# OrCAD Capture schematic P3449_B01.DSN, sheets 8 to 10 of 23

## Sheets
8 0015_Gigabit Ethernet POE: size Custom
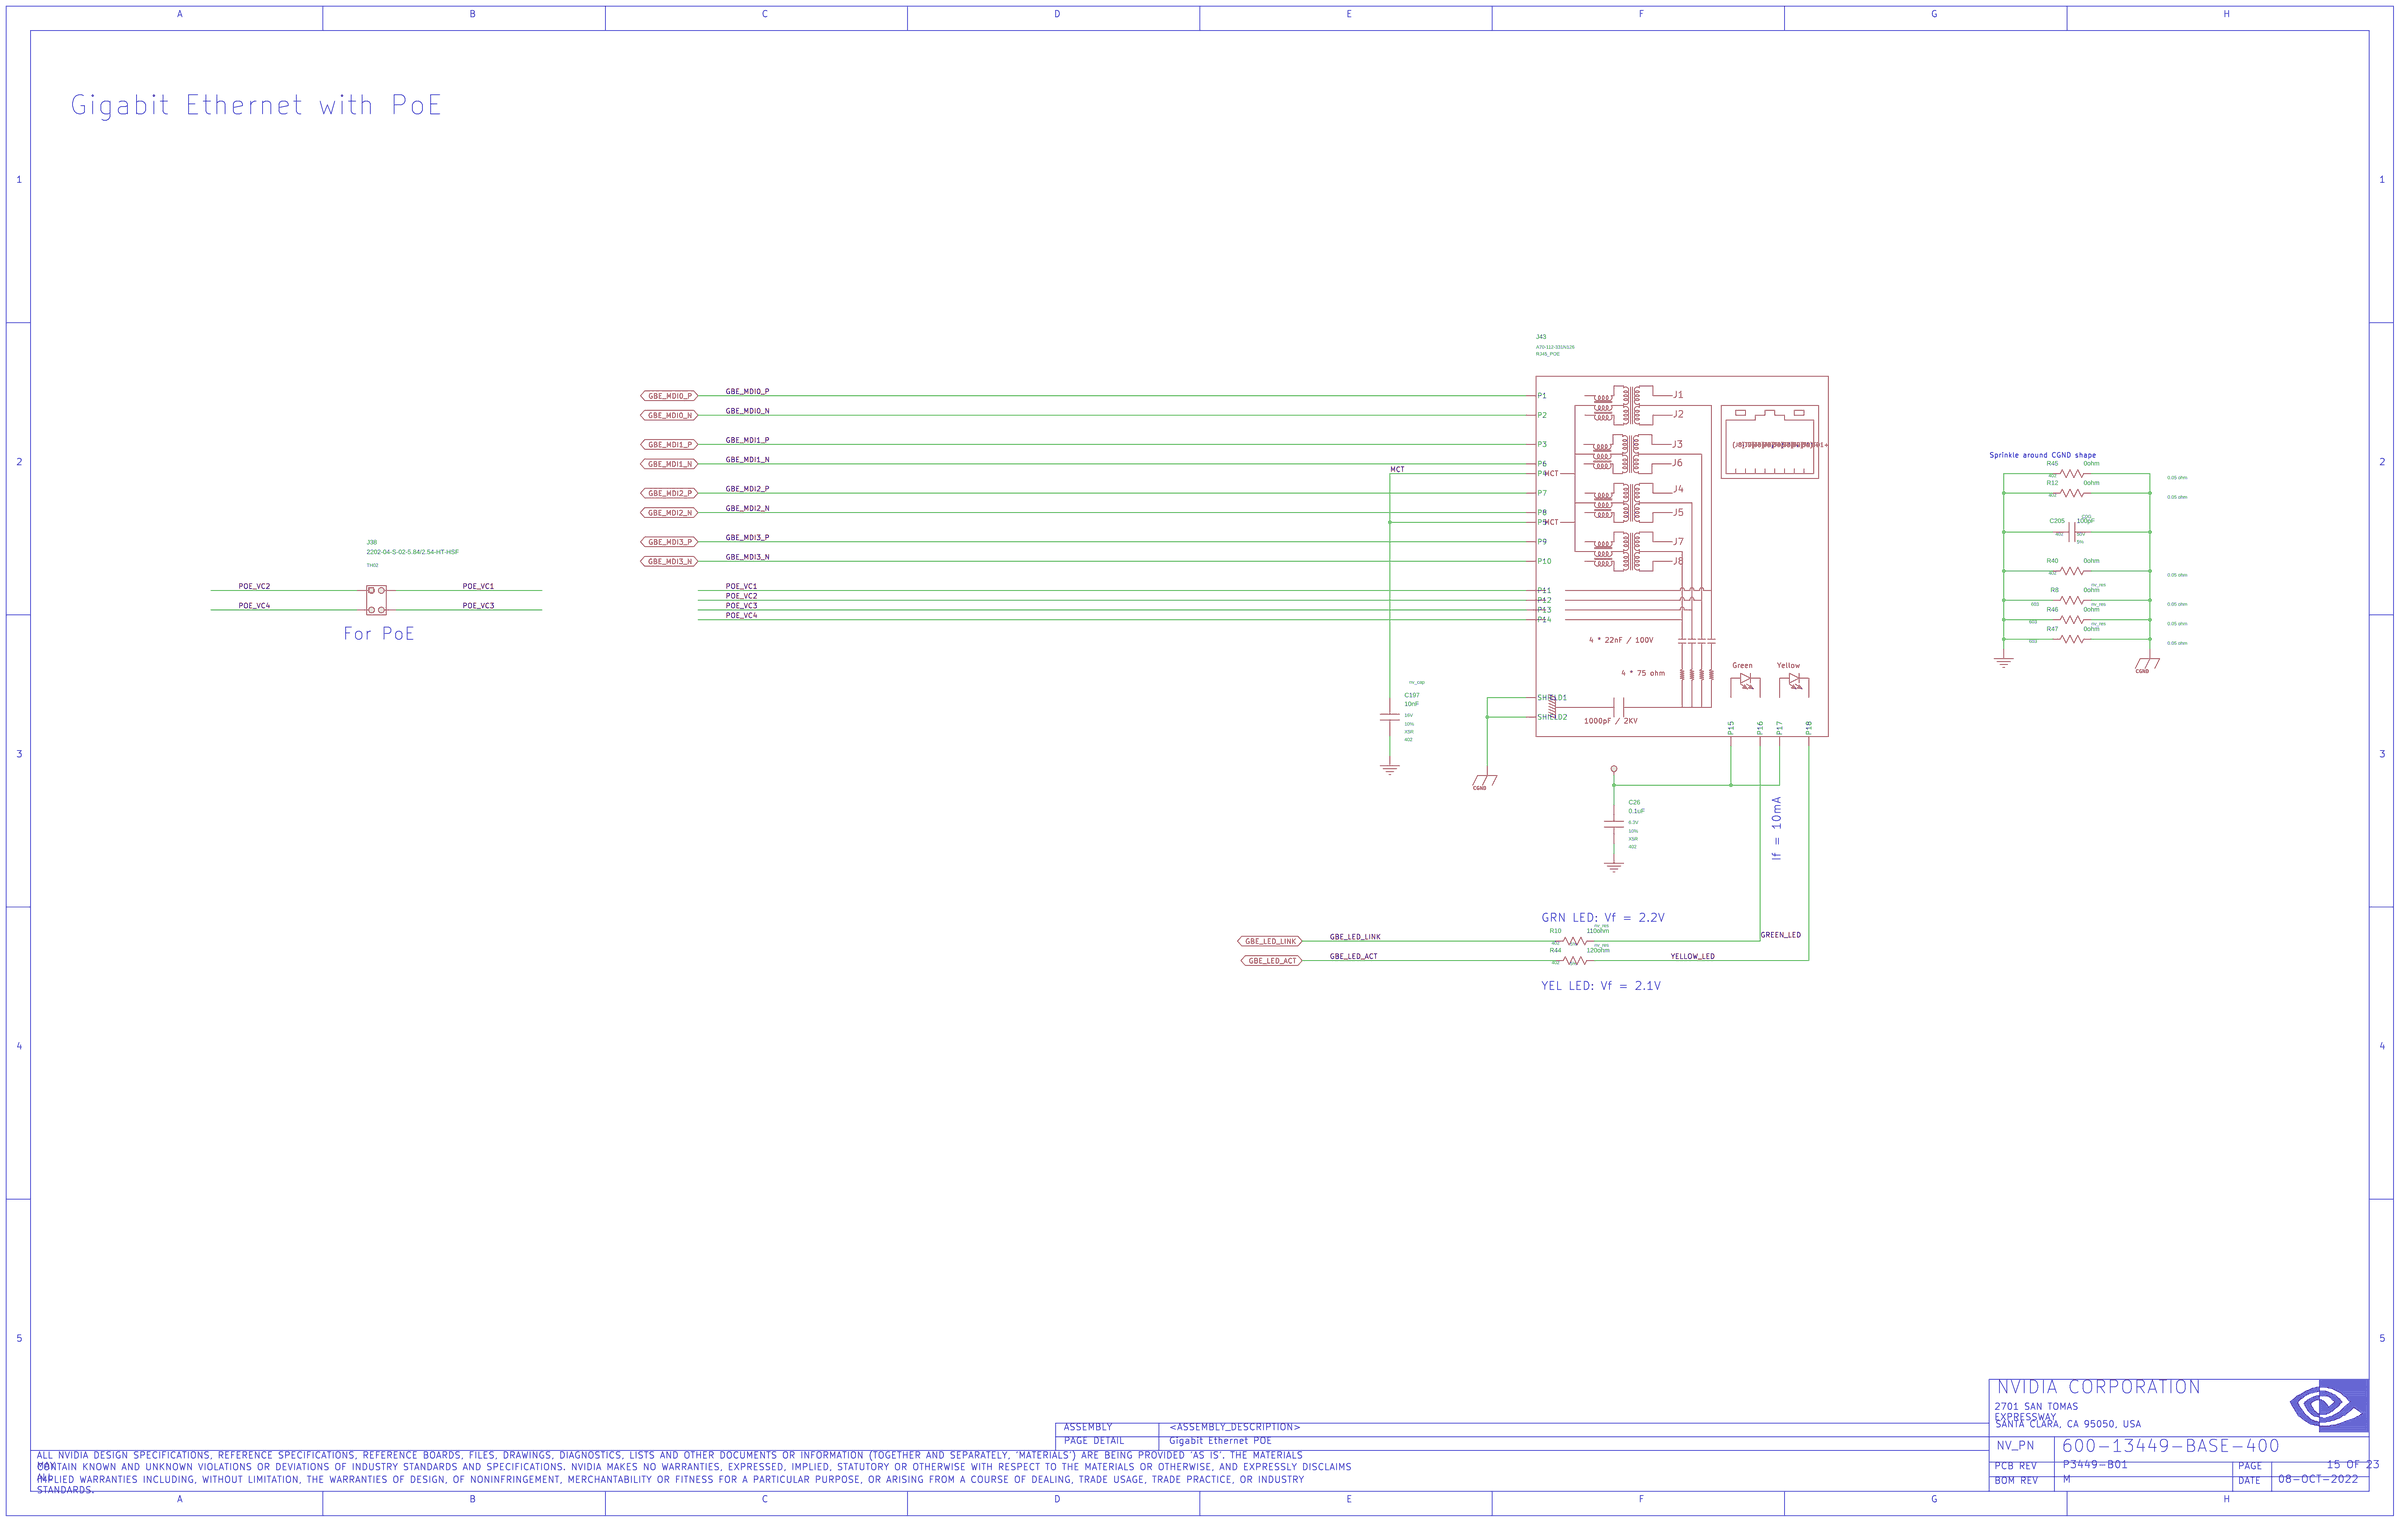
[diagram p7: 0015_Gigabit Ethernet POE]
9 0014_M.2 Key-E: size Custom
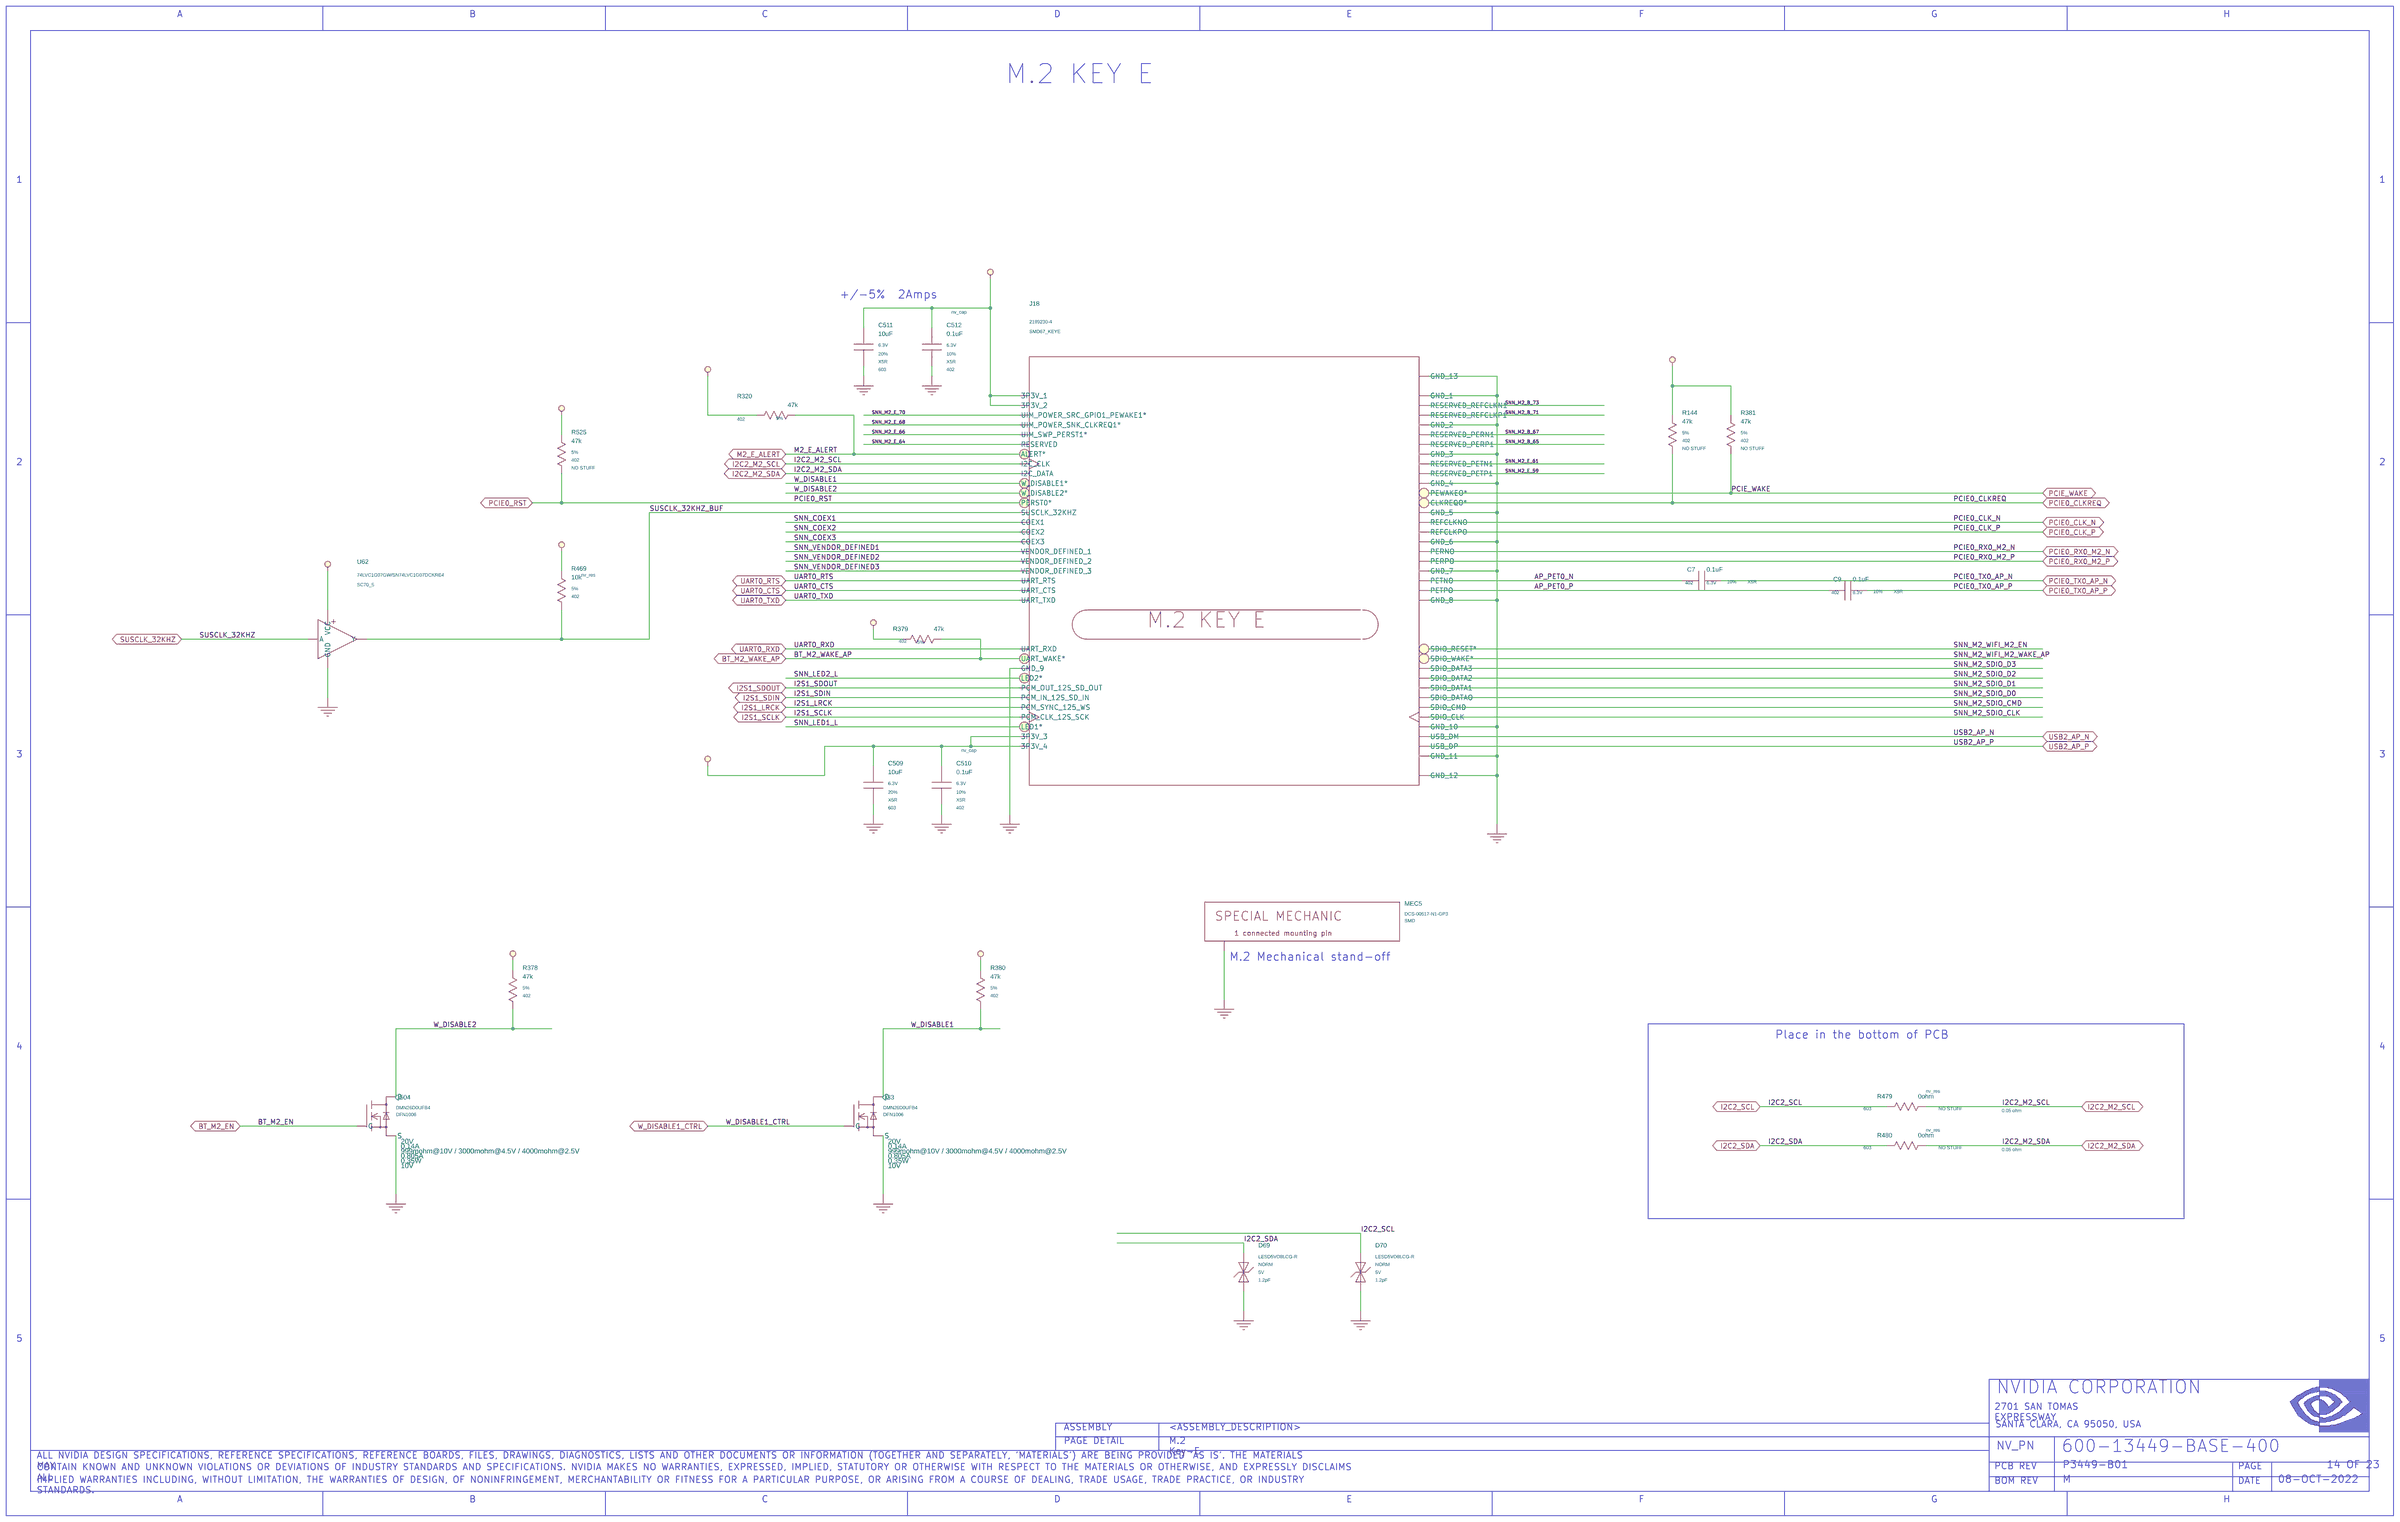
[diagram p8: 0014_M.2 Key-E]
10 0013_Power ON_OFF Logic: size Custom
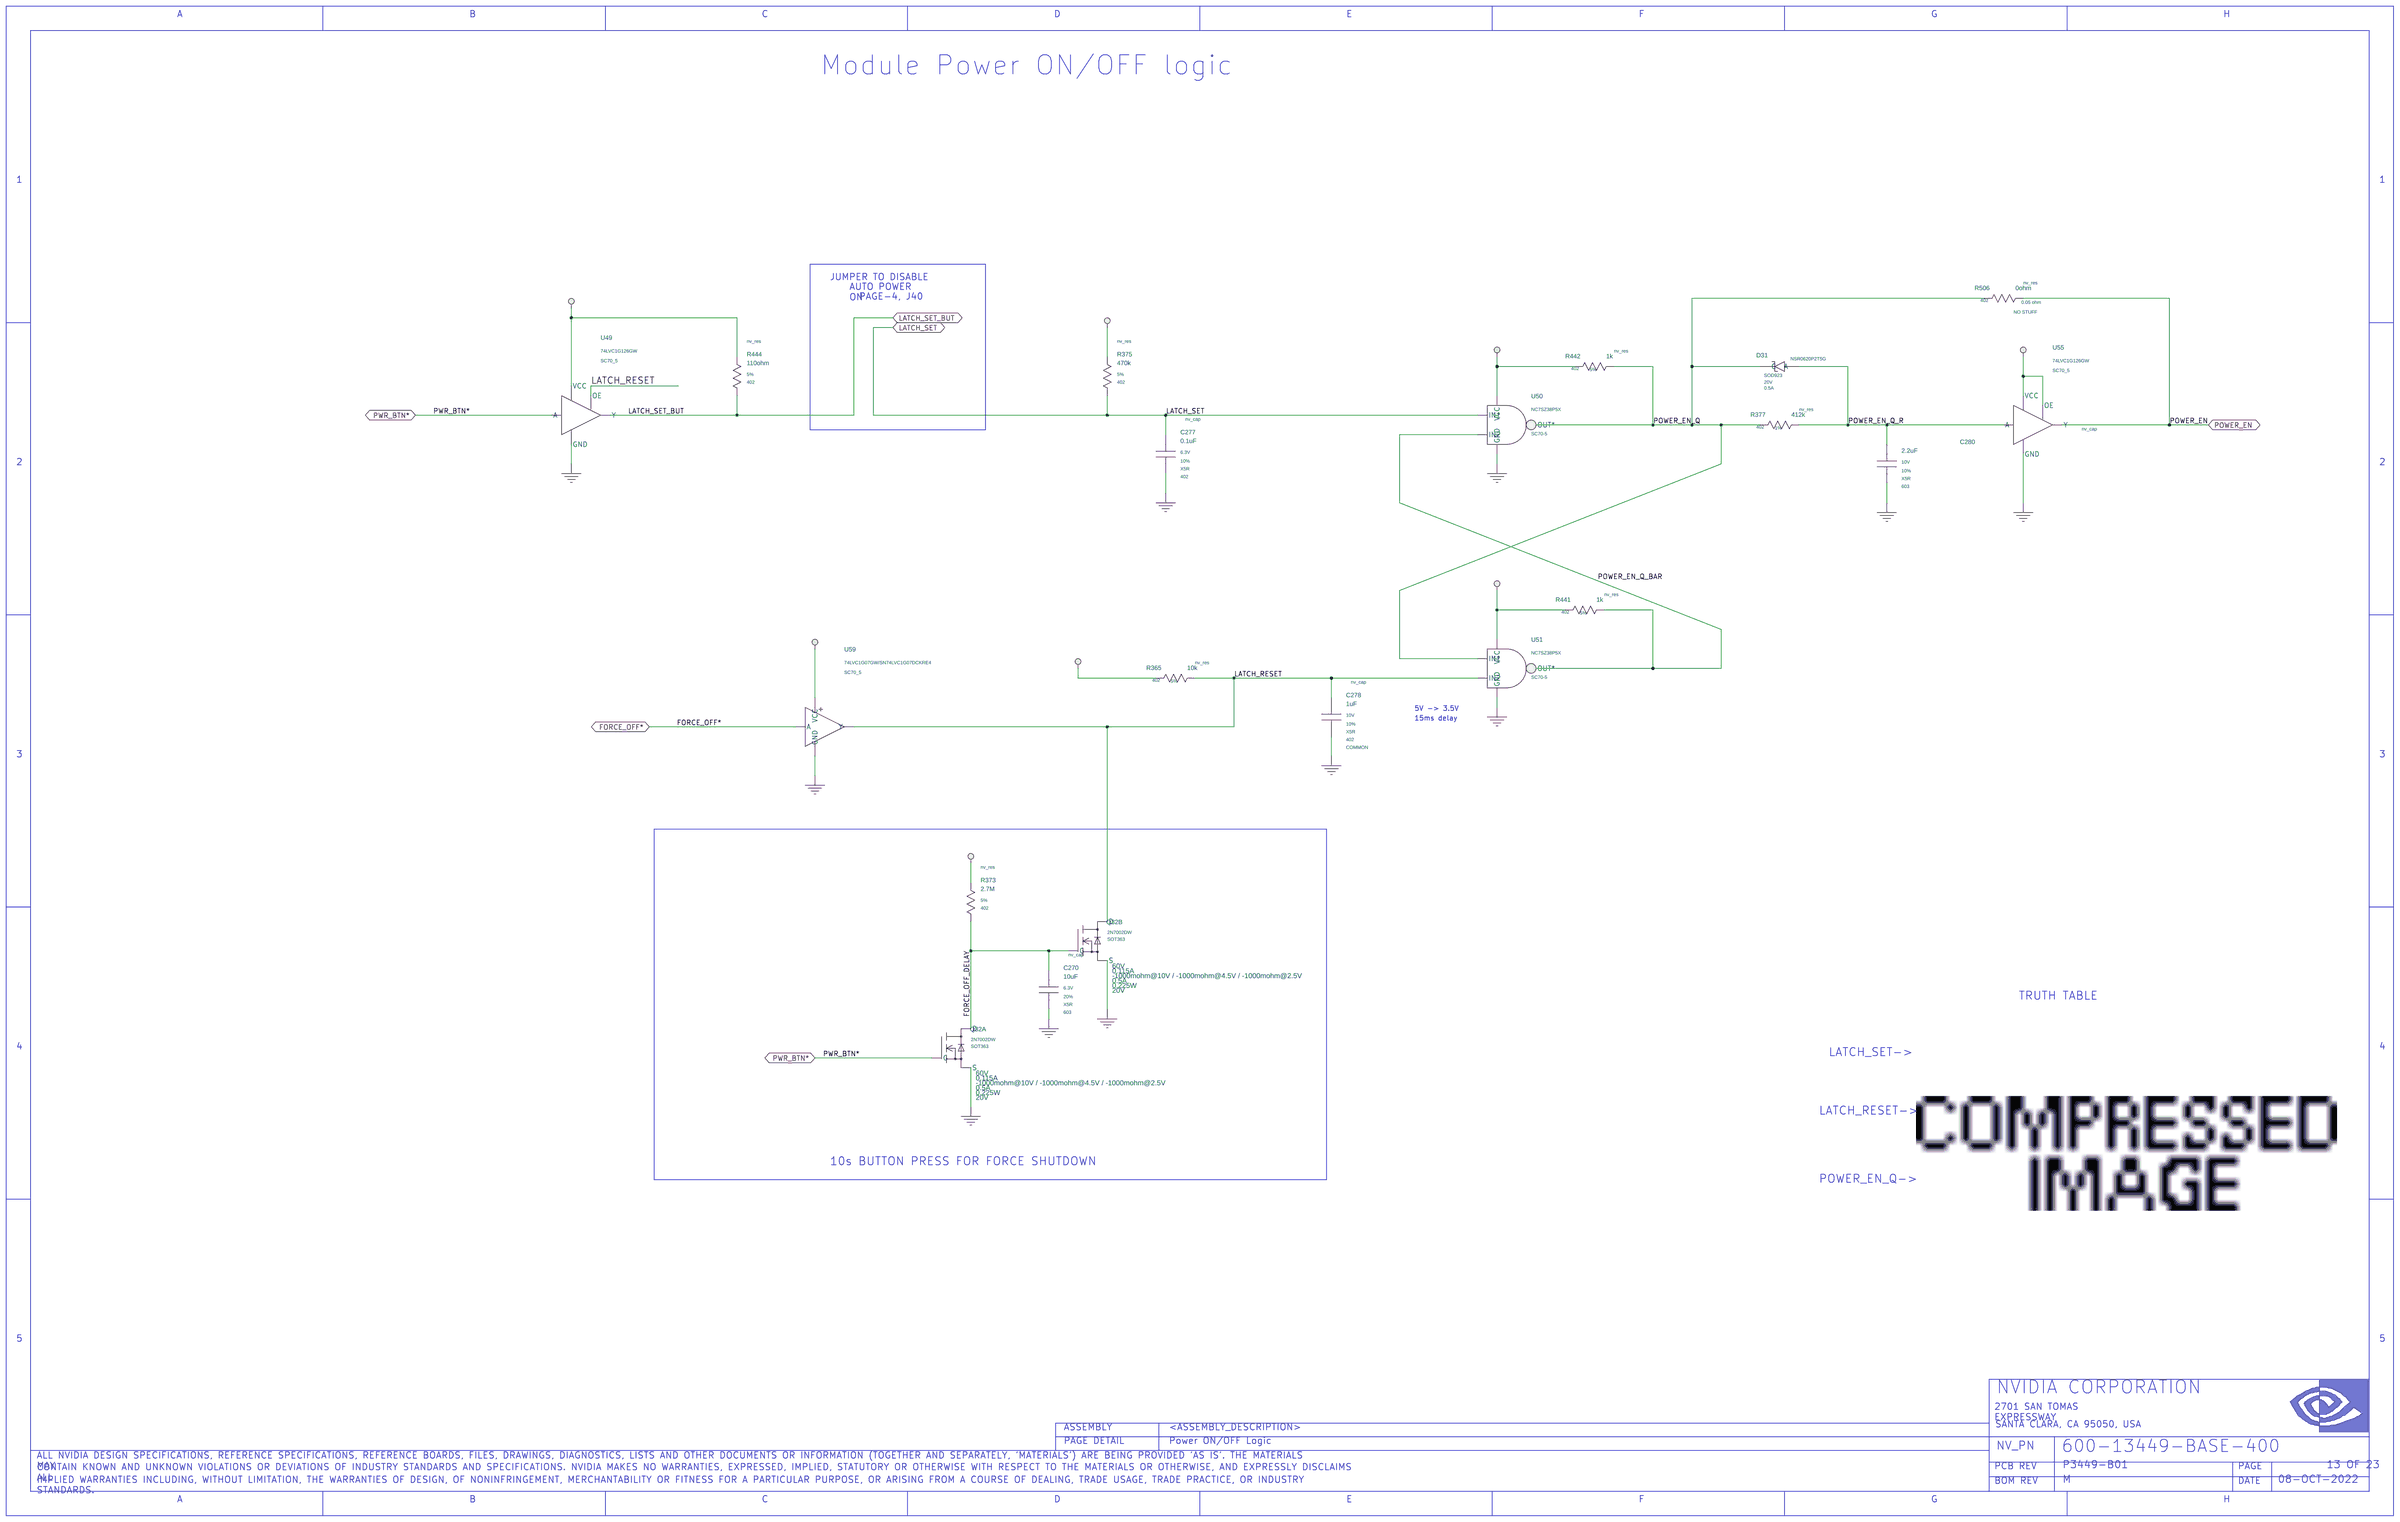
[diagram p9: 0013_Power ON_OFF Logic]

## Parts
sheet 0013_Power ON_OFF Logic
C270  10uF  [603]
C277  0.1uF  [402]
C278  1uF  [402]
C280  2.2uF  [603]
D31  D_SCHOTTKY  [DIODE_SMD_SOD923]
Q32  Q_FET_N_ENH  [SC70_6]  (sections A,B)
R365  10k  [402]
R373  2.7M  [402]
R375  470k  [402]
R377  412k  [402]
R441  1k  [402]
R442  1k  [402]
R444  110ohm  [402]
R506  0ohm  [402]
U49  U_BUF_3_STATE  [SC70_5]
U50  U_NAND_2IN  [SC70_5]
U51  U_NAND_2IN  [SC70_5]
U55  U_BUF_3_STATE  [SC70_5]
U59  U_BUF_OD  [SC70_5]
sheet 0014_M.2 Key-E
C7  0.1uF  [402]
C9  0.1uF  [402]
C509  10uF  [603]
C510  0.1uF  [402]
C511  10uF  [603]
C512  0.1uF  [402]
D69  D_ESD  [DIODE_SMD_010X060]
D70  D_ESD  [DIODE_SMD_010X060]
J18  CON_M2_PCI_EXP  [CON_MINIPEX_067_SMT_RA_M2_KEYE]
MEC5  MECH_SPECIAL  [MEC_STANDOFF_PTH_620C380P]
Q33  Q_FET_N_ENH  [DFET_003_SMD_010X006_B]
Q504  Q_FET_N_ENH  [DFET_003_SMD_010X006_B]
R144  47k  [402]
R320  47k  [402]
R378  47k  [402]
R379  47k  [402]
R380  47k  [402]
R381  47k  [402]
R469  10k  [402]
R479  0ohm  [603]
R480  0ohm  [603]
R525  47k  [402]
U62  U_BUF_OD  [SC70_5]
sheet 0015_Gigabit Ethernet POE
C26  0.1uF  [402]
C197  10nF  [402]
C205  100pF  [402]
J38  HDR_2X2  [CON_HDR_002X002_TH_ST_M_P025_B]
J43  CON_RJ45  [CON_RJ45_018_TH_RA_F_2LED]
R8  0ohm  [603]
R10  110ohm  [402]
R12  0ohm  [402]
R40  0ohm  [402]
R44  120ohm  [402]
R45  0ohm  [402]
R46  0ohm  [603]
R47  0ohm  [603]

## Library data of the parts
C270 = C#1: ASSEMBLY: POWER_ON_LOGIC; CDS_LIB: discrete; CDS_PART_NAME: C_0603-10UF,X5R,20%,6.3V,039-0135-000; CDS_PHYS_PART_NAME: C_0603-10UF,X5R,20%,6.3V,039-0135-000-039-0135-000,10UF; CDS_SEC: 1; CHIPS_PART_NAME: C; DEVICE_TYPENAME: C_0603-10UFX5R2063V039-0135-000-039-0135-00010UF; DRAWING: @P3449_B01_LIB.P3449_B01(SCH_1):PAGE13; MAT: X5R; MAX_VOLTAGE: 6.3V; NV_PN: 039-0135-000; PATH: I70; PHYS_PAGE: 13; ROT: 0; SEC: 1; SIGNAL_MODEL: nv_cap; TOL: 20%; VER: 1; XY: (-6800,2550)
C277 = C#1: ASSEMBLY: M2_WIFIBT; CDS_LIB: discrete; CDS_LOCATION: C510; CDS_PART_NAME: C_0402-0.1UF,X5R,10%,6.3V,039-0007-000; CDS_PHYS_PART_NAME: C_0402-0.1UF,X5R,10%,6.3V,039-0007-000-0.1UF,039-0007-000; CDS_SEC: 1; CHIPS_PART_NAME: C; DEVICE_TYPENAME: C_0402-01UFX5R1063V039-0007-000-01UF039-0007-000; DRAWING: @P3449_B01_LIB.P3449_B01(SCH_1):PAGE14; LOCATION: C510; MAT: X5R; MAX_VOLTAGE: 6.3V; NV_PN: 039-0007-000; PATH: I68; PHYS_PAGE: 14; ROT: 0; SEC: 1; SIGNAL_MODEL: nv_cap; TOL: 10%; VER: 1; XY: (-7650,5100)
C278 = C#1: ASSEMBLY: POWER_ON_LOGIC; CDS_LIB: discrete; CDS_PART_NAME: C_0402-1UF,X5R,10%,6.3V,039-0014-000; CDS_PHYS_PART_NAME: C_0402-1UF,X5R,10%,6.3V,039-0014-000-0.47UF,039-0014-000; CDS_SEC: 1; CHIPS_PART_NAME: C; DEVICE_TYPENAME: C_0402-1UFX5R1063V039-0014-000-047UF039-0014-000; DRAWING: @P3449_B01_LIB.P3449_B01(SCH_1):PAGE13; IMPLEMENTATION_TYPE: X^@REFDES  %1    %2   @NV_PN; MAT: X5R; MAX_VOLTAGE: 10V; NV_PN: 039-0014-000; PATH: I29; PHYS_PAGE: 13; PSPICETEMPLATE: Pspice Model; ROT: 0; SEC: 1; SIGNAL_MODEL: nv_cap; SKU: COMMON; TOL: 10%; VER: 1; XY: (-5350,3950)
C280 = C#1: ASSEMBLY: POWER_ON_LOGIC; CDS_LIB: discrete; CDS_PART_NAME: C_0603-1UF,X5R,10%,10V,039-0038-000; CDS_PHYS_PART_NAME: C_0603-1UF,X5R,10%,10V,039-0038-000-039-0038-000,1UF; CDS_SEC: 1; CHIPS_PART_NAME: C; DEVICE_TYPENAME: C_0603-1UFX5R1010V039-0038-000-039-0038-0001UF; DRAWING: @P3449_B01_LIB.P3449_B01(SCH_1):PAGE13; IMPLEMENTATION_TYPE: X^@REFDES  %1    %2   @NV_PN; MAT: X5R; MAX_VOLTAGE: 10V; NV_PN: 039-0038-000; PATH: I44; PHYS_PAGE: 13; PSPICETEMPLATE: Pspice Model; ROT: 0; SEC: 1; SIGNAL_MODEL: nv_cap; TOL: 10%; VER: 1; XY: (-2500,5250)
D31 = D_SCHOTTKY: ASSEMBLY: POWER_ON_LOGIC; CDS_LIB: discrete; CDS_PART_NAME: D_SCHOTTKY_SOD923-NSR0620P2T5G,SINGLE,20V,1A,0.52V@0.5A,0.5A,090-0096-000; CDS_PHYS_PART_NAME: D_SCHOTTKY_SOD923-NSR0620P2T5G,SINGLE,20V,1A,0.52V@0.5A,0.5A,090-0096-000-090-0096-000; CDS_SEC: 1; CONFIGURATION: Single; CONTINUOUS_CURRENT: 0.5A; DEVICE_TYPENAME: D_SCHOTTKY_SOD923-NSR0620P2T5GSINGLE20V1A052V05A05A090-0096-000-090-0096-000; DRAWING: @P3449_B01_LIB.P3449_B01(SCH_1):PAGE13; FORWARD_VOLTAGE: 0.52V@0.5A; MAX_CURRENT: 1A; MAX_VOLTAGE: 20V; NV_NAME: NSR0620P2T5G; NV_PN: 090-0096-000; PACK_TYPE: SOD923; PATH: I81; PHYS_PAGE: 13; ROT: 0; SEC: 1; VER: 1; XY: (-3050,5750)
Q32 = Q_FET_N_ENH: ASSEMBLY: POWER_ON_LOGIC; CDS_LIB: discrete; CDS_PART_NAME: Q_FET_N_ENH_SOT363-2N7002DW,60V,-1000MOHM@10V / -1000MOHM@4.5V / -1000MOHM@2.5V,0.115A,0.5A,20V,0.225W,[ ]@10V / 9999NC@4.5V /A; CDS_PHYS_PART_NAME: Q_FET_N_ENH_SOT363-2N7002DW,60V,-1000MOHM@10V / -1000MOHM@4.5V / -1000MOHM@2.5V,0.115A,0.5A,20V,0.225W,[ ]@10V / 9999NC@4.5V /B; CDS_SEC: 2; CONTINUOUS_CURRENT: 0.115A; DEVICE_TYPENAME: Q_FET_N_ENH_SOT363-2N7002DW60V-1000MOHM10V-1000MOHM45V-1000MOHM25V0115A05A20V0225W10V9999NC45VB; DRAWING: @P3449_B01_LIB.P3449_B01(SCH_1):PAGE13; MAX_CURRENT: 0.5A; MAX_VOLTAGE: 60V; MAX_WATTAGE: 0.225W; NV_NAME: 2N7002DW; NV_PN: 300-0560-000; PACK_TYPE: SOT363; PATH: I63; PHYS_PAGE: 13; Q_G: [ ]@10V / 9999nC@4.5V / [ ]@2.5V; ROT: 0; R_DS_ON: -1000mohm@10V / -1000mohm@4.5V / -1000mohm@2.5V; SEC: 2; VER: 2; V_BE_GS: 20V; XY: (-6600,2800)
R365 = R#1: ASSEMBLY: POWER_ON_LOGIC; CDS_LIB: discrete; CDS_PART_NAME: R_0402-10K,5 %,62.5MW,195-0486-000; CDS_PHYS_PART_NAME: R_0402-10K,5 %,62.5MW,195-0486-000-10K,195-0486-000; CDS_SEC: 1; CHIPS_PART_NAME: R; DEVICE_TYPENAME: R_0402-10K5625MW195-0486-000-10K195-0486-000; DRAWING: @P3449_B01_LIB.P3449_B01(SCH_1):PAGE13; IMPLEMENTATION_TYPE: X^@REFDES  %1    %2   @NV_PN; MAX_WATTAGE: 62.5mW; NV_PN: 195-0486-000; PATH: I39; PHYS_PAGE: 13; PSPICETEMPLATE: Pspice Model; ROT: 0; SEC: 1; SIGNAL_MODEL: nv_res; TOL: 5%; VER: 1; XY: (-6150,4150)
R373 = R: ASSEMBLY: POWER_ON_LOGIC; CDS_LIB: discrete; CDS_PART_NAME: R_0402-2.7M,5 %,62.5MW,195-0559-000; CDS_PHYS_PART_NAME: R_0402-2.7M,5 %,62.5MW,195-0559-000-195-0559-000,2.7M; CDS_SEC: 1; DEVICE_TYPENAME: R_0402-27M5625MW195-0559-000-195-0559-00027M; DRAWING: @P3449_B01_LIB.P3449_B01(SCH_1):PAGE13; MAX_WATTAGE: 62.5mW; NV_PN: 195-0559-000; PATH: I69; PHYS_PAGE: 13; ROT: 0; SEC: 1; SIGNAL_MODEL: nv_res; TOL: 5%; VER: 2; XY: (-7200,3000)
R375 = R: ASSEMBLY: POWER_ON_LOGIC; CDS_LIB: discrete; CDS_PART_NAME: R_0402-470K,5 %,62.5MW,195-0600-000; CDS_PHYS_PART_NAME: R_0402-470K,5 %,62.5MW,195-0600-000-195-0600-000,470K; CDS_SEC: 1; DEVICE_TYPENAME: R_0402-470K5625MW195-0600-000-195-0600-000470K; DRAWING: @P3449_B01_LIB.P3449_B01(SCH_1):PAGE13; MAX_WATTAGE: 62.5mW; NV_PN: 195-0600-000; PATH: I54; PHYS_PAGE: 13; ROT: 0; SEC: 1; SIGNAL_MODEL: nv_res; TOL: 5%; VER: 2; XY: (-6500,5700)
R377 = R#1: ASSEMBLY: POWER_ON_LOGIC; CDS_LIB: discrete; CDS_PART_NAME: R_0402-470K,5 %,62.5MW,195-0600-000; CDS_PHYS_PART_NAME: R_0402-470K,5 %,62.5MW,195-0600-000-195-0600-000,470K; CDS_SEC: 1; CHIPS_PART_NAME: R; DEVICE_TYPENAME: R_0402-470K5625MW195-0600-000-195-0600-000470K; DRAWING: @P3449_B01_LIB.P3449_B01(SCH_1):PAGE13; IMPLEMENTATION_TYPE: X^@REFDES  %1    %2   @NV_PN; MAX_WATTAGE: 62.5mW; NV_PN: 195-0600-000; PATH: I45; PHYS_PAGE: 13; PSPICETEMPLATE: Pspice Model; ROT: 0; SEC: 1; SIGNAL_MODEL: nv_res; TOL: 1%; VER: 1; XY: (-3050,5450)
R441 = R#1: ASSEMBLY: POWER_ON_LOGIC; CDS_LIB: discrete; CDS_PART_NAME: R_0402-1K,5 %,62.5MW,195-0485-000; CDS_PHYS_PART_NAME: R_0402-1K,5 %,62.5MW,195-0485-000-195-0485-000,1K; CDS_SEC: 1; CHIPS_PART_NAME: R; DEVICE_TYPENAME: R_0402-1K5625MW195-0485-000-195-0485-0001K; DRAWING: @P3449_B01_LIB.P3449_B01(SCH_1):PAGE13; MAX_WATTAGE: 62.5mW; NV_PN: 195-0485-000; PATH: I76; PHYS_PAGE: 13; ROT: 0; SEC: 1; SIGNAL_MODEL: nv_res; TOL: 5%; VER: 1; XY: (-4050,4500)
R442 = R#1: ASSEMBLY: POWER_ON_LOGIC; CDS_LIB: discrete; CDS_PART_NAME: R_0402-1K,5 %,62.5MW,195-0485-000; CDS_PHYS_PART_NAME: R_0402-1K,5 %,62.5MW,195-0485-000-195-0485-000,1K; CDS_SEC: 1; CHIPS_PART_NAME: R; DEVICE_TYPENAME: R_0402-1K5625MW195-0485-000-195-0485-0001K; DRAWING: @P3449_B01_LIB.P3449_B01(SCH_1):PAGE13; MAX_WATTAGE: 62.5mW; NV_PN: 195-0485-000; PATH: I75; PHYS_PAGE: 13; ROT: 0; SEC: 1; SIGNAL_MODEL: nv_res; TOL: 5%; VER: 1; XY: (-4000,5750)
R444 = R: ASSEMBLY: POWER_ON_LOGIC; CDS_LIB: discrete; CDS_PART_NAME: R_0402-110OHM,5 %,62.5MW,195-0492-000; CDS_PHYS_PART_NAME: R_0402-110OHM,5 %,62.5MW,195-0492-000-110OHM,195-0492-000; CDS_SEC: 1; DEVICE_TYPENAME: R_0402-110OHM5625MW195-0492-000-110OHM195-0492-000; DRAWING: @P3449_B01_LIB.P3449_B01(SCH_1):PAGE13; MAX_WATTAGE: 62.5mW; NV_PN: 195-0492-000; PATH: I77; PHYS_PAGE: 13; ROT: 0; SEC: 1; SIGNAL_MODEL: nv_res; TOL: 5%; VER: 2; XY: (-8400,5700)
R506 = R#1: ASSEMBLY: POWER_ON_LOGIC; CDS_LIB: discrete; CDS_PART_NAME: R_0402-0OHM,0.05 OHM,62.5MW,195-2655-000; CDS_PHYS_PART_NAME: R_0402-0OHM,0.05 OHM,62.5MW,195-2655-000-0OHM,195-2655-000; CDS_SEC: 1; CHIPS_PART_NAME: R; DEVICE_TYPENAME: R_0402-0OHM005OHM625MW195-2655-000-0OHM195-2655-000; DRAWING: @P3449_B01_LIB.P3449_B01(SCH_1):PAGE13; MAX_WATTAGE: 62.5mW; NV_PN: 195-2655-000; PATH: I88; PHYS_PAGE: 13; ROT: 0; SEC: 1; SIGNAL_MODEL: nv_res; SKU: NO STUFF; TOL: 0.05 ohm; VER: 1; XY: (-1900,6100)
U49 = U_BUF_3_STATE: ASSEMBLY: POWER_ON_LOGIC; CDS_LIB: logic; CDS_PART_NAME: U_BUF_3_STATE_SC70_5-74LVC1G126GW,BUFFER - TRI-STATE,115-1821-000; CDS_PHYS_PART_NAME: U_BUF_3_STATE_SC70_5-74LVC1G126GW,BUFFER - TRI-STATE,115-1821-000-115-1821-000; CDS_SEC: 1; DEVICE_TYPENAME: U_BUF_3_STATE_SC70_5-74LVC1G126GWBUFFER-TRI-STATE115-1821-000-115-1821-000; DRAWING: @P3449_B01_LIB.P3449_B01(SCH_1):PAGE13; FUNCTION: Buffer - Tri-state; NV_NAME: 74LVC1G126GW; NV_PN: 115-1821-000; PATH: I50; PHYS_PAGE: 13; ROT: 0; SEC: 1; VER: 10; XY: (-9200,5500)
U50 = U_NAND_2IN: ASSEMBLY: POWER_ON_LOGIC; CDS_LIB: logic; CDS_PART_NAME: U_NAND_2IN_SC70-5-NC7SZ38P5X,GATES - AND - 2 INPUT,115-0742-000; CDS_PHYS_PART_NAME: U_NAND_2IN_SC70-5-NC7SZ38P5X,GATES - AND - 2 INPUT,115-0742-000-115-0742-000; CDS_SEC: 1; DEVICE_TYPENAME: U_NAND_2IN_SC70-5-NC7SZ38P5XGATES-AND-2INPUT115-0742-000-115-0742-000; DRAWING: @P3449_B01_LIB.P3449_B01(SCH_1):PAGE13; FUNCTION: Gates - AND - 2 input; NV_NAME: NC7SZ38P5X; NV_PN: 115-0742-000; PACK_TYPE: SC70-5; PATH: I32; PHYS_PAGE: 13; ROT: 0; SEC: 1; VER: 1; XY: (-4450,5450)
U51 = U_NAND_2IN: ASSEMBLY: POWER_ON_LOGIC; CDS_LIB: logic; CDS_PART_NAME: U_NAND_2IN_SC70-5-NC7SZ38P5X,GATES - AND - 2 INPUT,115-0742-000; CDS_PHYS_PART_NAME: U_NAND_2IN_SC70-5-NC7SZ38P5X,GATES - AND - 2 INPUT,115-0742-000-115-0742-000; CDS_SEC: 1; DEVICE_TYPENAME: U_NAND_2IN_SC70-5-NC7SZ38P5XGATES-AND-2INPUT115-0742-000-115-0742-000; DRAWING: @P3449_B01_LIB.P3449_B01(SCH_1):PAGE13; FUNCTION: Gates - AND - 2 input; NV_NAME: NC7SZ38P5X; NV_PN: 115-0742-000; PACK_TYPE: SC70-5; PATH: I33; PHYS_PAGE: 13; ROT: 0; SEC: 1; VER: 1; XY: (-4450,4200)
U55 = U_BUF_3_STATE: ASSEMBLY: POWER_ON_LOGIC; CDS_LIB: logic; CDS_PART_NAME: U_BUF_3_STATE_SC70_5-74LVC1G126GW,BUFFER - TRI-STATE,115-1821-000; CDS_PHYS_PART_NAME: U_BUF_3_STATE_SC70_5-74LVC1G126GW,BUFFER - TRI-STATE,115-1821-000-115-1821-000; CDS_SEC: 1; DEVICE_TYPENAME: U_BUF_3_STATE_SC70_5-74LVC1G126GWBUFFER-TRI-STATE115-1821-000-115-1821-000; DRAWING: @P3449_B01_LIB.P3449_B01(SCH_1):PAGE13; FUNCTION: Buffer - Tri-state; NV_NAME: 74LVC1G126GW; NV_PN: 115-1821-000; PATH: I78; PHYS_PAGE: 13; ROT: 0; SEC: 1; VER: 10; XY: (-1750,5450)
U59 = U_BUF_OD: ASSEMBLY: POWER_ON_LOGIC; CDS_LIB: logic; CDS_PART_NAME: U_BUF_OD_SC70_5-74LVC1G07GW/SN74LVC1G07DCKRE4,BUFFER - OPEN DRAIN,115-0138-000; CDS_PHYS_PART_NAME: U_BUF_OD_SC70_5-74LVC1G07GW/SN74LVC1G07DCKRE4,BUFFER - OPEN DRAIN,115-0138-000-115-0138-000; CDS_SEC: 1; DEVICE_TYPENAME: U_BUF_OD_SC70_5-74LVC1G07GWSN74LVC1G07DCKRE4BUFFER-OPENDRAIN115-0138-000-115-0138-000; DRAWING: @P3449_B01_LIB.P3449_B01(SCH_1):PAGE13; FUNCTION: Buffer - Open Drain; NV_NAME: 74LVC1G07GW/SN74LVC1G07DCKRE4; NV_PN: 115-0138-000; PATH: I84; PHYS_PAGE: 13; ROT: 0; SEC: 1; VER: 1; XY: (-7950,3900)
C7 = C: ASSEMBLY: M2_WIFIBT; CDS_LIB: discrete; CDS_PART_NAME: C_0402-0.1UF,X5R,10%,6.3V,039-0007-000; CDS_PHYS_PART_NAME: C_0402-0.1UF,X5R,10%,6.3V,039-0007-000-0.1UF,039-0007-000; CDS_SEC: 1; DEVICE_TYPENAME: C_0402-01UFX5R1063V039-0007-000-01UF039-0007-000; DRAWING: @P3449_B01_LIB.P3449_B01(SCH_1):PAGE14; MAT: X5R; MAX_VOLTAGE: 6.3V; NV_PN: 039-0007-000; PATH: I166; PHYS_PAGE: 14; ROT: 0; SEC: 1; SIGNAL_MODEL: nv_cap; TOL: 10%; VER: 2; XY: (-3750,6150)
C9 = C: ASSEMBLY: M2_WIFIBT; CDS_LIB: discrete; CDS_PART_NAME: C_0402-0.1UF,X5R,10%,6.3V,039-0007-000; CDS_PHYS_PART_NAME: C_0402-0.1UF,X5R,10%,6.3V,039-0007-000-0.1UF,039-0007-000; CDS_SEC: 1; DEVICE_TYPENAME: C_0402-01UFX5R1063V039-0007-000-01UF039-0007-000; DRAWING: @P3449_B01_LIB.P3449_B01(SCH_1):PAGE14; MAT: X5R; MAX_VOLTAGE: 6.3V; NV_PN: 039-0007-000; PATH: I165; PHYS_PAGE: 14; ROT: 0; SEC: 1; SIGNAL_MODEL: nv_cap; TOL: 10%; VER: 2; XY: (-3000,6100)
C509 = C#1: ASSEMBLY: M2_WIFIBT; CDS_LIB: discrete; CDS_PART_NAME: C_0603-10UF,X5R,20%,6.3V,039-0135-000; CDS_PHYS_PART_NAME: C_0603-10UF,X5R,20%,6.3V,039-0135-000-039-0135-000,10UF; CDS_SEC: 1; CHIPS_PART_NAME: C; DEVICE_TYPENAME: C_0603-10UFX5R2063V039-0135-000-039-0135-00010UF; DRAWING: @P3449_B01_LIB.P3449_B01(SCH_1):PAGE14; MAT: X5R; MAX_VOLTAGE: 6.3V; NV_PN: 039-0135-000; PATH: I70; PHYS_PAGE: 14; ROT: 0; SEC: 1; SIGNAL_MODEL: DEFAULT_CAPACITOR_1e+07pF_2_1; TOL: 20%; VER: 1; XY: (-8000,5100)
C510 = C#1: ASSEMBLY: M2_WIFIBT; CDS_LIB: discrete; CDS_PART_NAME: C_0402-0.1UF,X5R,10%,6.3V,039-0007-000; CDS_PHYS_PART_NAME: C_0402-0.1UF,X5R,10%,6.3V,039-0007-000-0.1UF,039-0007-000; CDS_SEC: 1; CHIPS_PART_NAME: C; DEVICE_TYPENAME: C_0402-01UFX5R1063V039-0007-000-01UF039-0007-000; DRAWING: @P3449_B01_LIB.P3449_B01(SCH_1):PAGE14; MAT: X5R; MAX_VOLTAGE: 6.3V; NV_PN: 039-0007-000; PATH: I68; PHYS_PAGE: 14; ROT: 0; SEC: 1; SIGNAL_MODEL: nv_cap; TOL: 10%; VER: 1; XY: (-7650,5100)
C511 = C#1: ASSEMBLY: M2_WIFIBT; CDS_LIB: discrete; CDS_PART_NAME: C_0603-10UF,X5R,20%,6.3V,039-0135-000; CDS_PHYS_PART_NAME: C_0603-10UF,X5R,20%,6.3V,039-0135-000-039-0135-000,10UF; CDS_SEC: 1; CHIPS_PART_NAME: C; DEVICE_TYPENAME: C_0603-10UFX5R2063V039-0135-000-039-0135-00010UF; DRAWING: @P3449_B01_LIB.P3449_B01(SCH_1):PAGE14; MAT: X5R; MAX_VOLTAGE: 6.3V; NV_PN: 039-0135-000; PATH: I57; PHYS_PAGE: 14; ROT: 0; SEC: 1; SIGNAL_MODEL: DEFAULT_CAPACITOR_1e+07pF_2_1; TOL: 20%; VER: 1; XY: (-8050,7350)
C512 = C#1: ASSEMBLY: M2_WIFIBT; CDS_LIB: discrete; CDS_PART_NAME: C_0402-0.1UF,X5R,10%,6.3V,039-0007-000; CDS_PHYS_PART_NAME: C_0402-0.1UF,X5R,10%,6.3V,039-0007-000-0.1UF,039-0007-000; CDS_SEC: 1; CHIPS_PART_NAME: C; DEVICE_TYPENAME: C_0402-01UFX5R1063V039-0007-000-01UF039-0007-000; DRAWING: @P3449_B01_LIB.P3449_B01(SCH_1):PAGE14; MAT: X5R; MAX_VOLTAGE: 6.3V; NV_PN: 039-0007-000; PATH: I56; PHYS_PAGE: 14; ROT: 0; SEC: 1; SIGNAL_MODEL: nv_cap; TOL: 10%; VER: 1; XY: (-7700,7350)
D69 = D_ESD: ASSEMBLY: M2_WIFIBT; BREAKDOWN_VOLTAGE_MIN_TYP: 5.5V; CAPACITANCE_MAX_TYP: 1.2pF; CDS_LIB: discrete; CDS_PART_NAME: D_ESD_NORM-LESD5VD8LCG-R,1 LINE,BI-DIRECTIONAL,5V,0.05UA,5.5V,10V@2A,1.2PF,090-0172-000; CDS_PHYS_PART_NAME: D_ESD_NORM-LESD5VD8LCG-R,1 LINE,BI-DIRECTIONAL,5V,0.05UA,5.5V,10V@2A,1.2PF,090-0172-000-090-0172-000; CDS_SEC: 1; CLAMPING_VOLTAGE: 10V@2A; CONFIGURATION: 1 Line; DEVICE_TYPENAME: D_ESD_NORM-LESD5VD8LCG-R1LINEBI-DIRECTIONAL5V005UA55V10V2A12PF090-0172-000-090-0172-000; DRAWING: @P3449_B01_LIB.P3449_B01(SCH_1):PAGE14; MAX_REVERSE_LEAKAGE_CURRENT: 0.05uA; MAX_REVERSE_VOLTAGE: 5V; NV_NAME: LESD5VD8LCG-R; NV_PN: 090-0172-000; PACK_TYPE: NORM; PATH: I161; PHYS_PAGE: 14; POLARITY: Bi-Directional; ROT: 0; SEC: 1; VER: 2; XY: (-6100,2600)
D70 = D_ESD: ASSEMBLY: M2_WIFIBT; BREAKDOWN_VOLTAGE_MIN_TYP: 5.5V; CAPACITANCE_MAX_TYP: 1.2pF; CDS_LIB: discrete; CDS_PART_NAME: D_ESD_NORM-LESD5VD8LCG-R,1 LINE,BI-DIRECTIONAL,5V,0.05UA,5.5V,10V@2A,1.2PF,090-0172-000; CDS_PHYS_PART_NAME: D_ESD_NORM-LESD5VD8LCG-R,1 LINE,BI-DIRECTIONAL,5V,0.05UA,5.5V,10V@2A,1.2PF,090-0172-000-090-0172-000; CDS_SEC: 1; CLAMPING_VOLTAGE: 10V@2A; CONFIGURATION: 1 Line; DEVICE_TYPENAME: D_ESD_NORM-LESD5VD8LCG-R1LINEBI-DIRECTIONAL5V005UA55V10V2A12PF090-0172-000-090-0172-000; DRAWING: @P3449_B01_LIB.P3449_B01(SCH_1):PAGE14; MAX_REVERSE_LEAKAGE_CURRENT: 0.05uA; MAX_REVERSE_VOLTAGE: 5V; NV_NAME: LESD5VD8LCG-R; NV_PN: 090-0172-000; PACK_TYPE: NORM; PATH: I162; PHYS_PAGE: 14; POLARITY: Bi-Directional; ROT: 0; SEC: 1; VER: 2; XY: (-5500,2600)
J18 = CON_M2_PCI_EXP: ANGLE: 90; ASSEMBLY: M2_WIFIBT; CDS_LIB: electro_mechanic; CDS_PART_NAME: CON_M2_PCI_EXP_SMD67_KEYE-2199230-4,FEMALE,0.5MM,90,N/A,NO,NO,NO,NO,50.0 V,0.5 A,080-1243-000; CDS_PHYS_PART_NAME: CON_M2_PCI_EXP_SMD67_KEYE-2199230-4,FEMALE,0.5MM,90,N/A,NO,NO,NO,NO,50.0 V,0.5 A,080-1243-000-080-1243-000; CDS_SEC: 1; DEVICE_TYPENAME: CON_M2_PCI_EXP_SMD67_KEYE-2199230-4FEMALE05MM90NANONONONO500V05A080-1243-000-080-1243-000; DRAWING: @P3449_B01_LIB.P3449_B01(SCH_1):PAGE14; EMI_GROUND_TAB: NO; GENDER: FEMALE; LATCHING: NO; MAX_CURRENT: 0.5 A; MAX_VOLTAGE: 50.0 V; NV_NAME: 2199230-4; NV_PN: 080-1243-000; PACK_TYPE: SMD67_KEYE; PATH: I1; PHYS_PAGE: 14; PITCH: 0.5mm; REFLOW: N/A; ROT: 0; SEC: 1; SHIELDED: NO; SHROUDED: NO; VER: 2; XY: (-6200,6200)
MEC5 = MECH_SPECIAL: ASSEMBLY: M2_WIFIBT; CDS_LIB: mechanic; CDS_PART_NAME: MECH_SPECIAL_SMD-DCS-00517-N1-GP3,155-0697-000; CDS_PHYS_PART_NAME: MECH_SPECIAL_SMD-DCS-00517-N1-GP3,155-0697-000-155-0697-000; CDS_SEC: 1; DEVICE_TYPENAME: MECH_SPECIAL_SMD-DCS-00517-N1-GP3155-0697-000-155-0697-000; DRAWING: @P3449_B01_LIB.P3449_B01(SCH_1):PAGE14; NV_NAME: DCS-00517-N1-GP3; NV_PN: 155-0697-000; PACK_TYPE: SMD; PATH: I146; PHYS_PAGE: 14; ROT: 0; SEC: 1; VER: 2; XY: (-5800,4400)
Q33 = Q_FET_N_ENH#1: ASSEMBLY: M2_WIFIBT; CDS_LIB: discrete; CDS_PART_NAME: Q_FET_N_ENH_DFN1006-DMN26D0UFB4,20V,999MOHM@10V / 3000MOHM@4.5V / 4000MOHM@2.5V,0.14A,0.805A,10V,0.35W,999NC@10V / 0NC@4.5V / A; CDS_PHYS_PART_NAME: Q_FET_N_ENH_DFN1006-DMN26D0UFB4,20V,999MOHM@10V / 3000MOHM@4.5V / 4000MOHM@2.5V,0.14A,0.805A,10V,0.35W,999NC@10V / 0NC@4.5V / B; CDS_SEC: 1; CONTINUOUS_CURRENT: 0.14A; CaptureCellPackProp: Q_FET_N_ENH##1; DEVICE_TYPENAME: Q_FET_N_ENH_DFN1006-DMN26D0UFB420V999MOHM10V3000MOHM45V4000MOHM25V014A0805A10V035W999NC10V0NC45VB; DRAWING: @P3449_B01_LIB.P3449_B01(SCH_1):PAGE14; MAX_CURRENT: 0.805A; MAX_VOLTAGE: 20V; MAX_WATTAGE: 0.35W; NV_NAME: DMN26D0UFB4; NV_PN: 300-0868-000; PACK_TYPE: DFN1006; PATH: I126; PHYS_PAGE: 14; Q_G: 999nC@10V / 0nC@4.5V / 999nC@2.5V; ROT: 0; R_DS_ON: 999mohm@10V / 3000mohm@4.5V / 4000mohm@2.5V; SEC: 1; VER: 2; V_BE_GS: 10V; XY: (-8050,3400)
Q504 = Q_FET_N_ENH#1: ASSEMBLY: M2_WIFIBT; CDS_LIB: discrete; CDS_PART_NAME: Q_FET_N_ENH_DFN1006-DMN26D0UFB4,20V,999MOHM@10V / 3000MOHM@4.5V / 4000MOHM@2.5V,0.14A,0.805A,10V,0.35W,999NC@10V / 0NC@4.5V / A; CDS_PHYS_PART_NAME: Q_FET_N_ENH_DFN1006-DMN26D0UFB4,20V,999MOHM@10V / 3000MOHM@4.5V / 4000MOHM@2.5V,0.14A,0.805A,10V,0.35W,999NC@10V / 0NC@4.5V / B; CDS_SEC: 1; CONTINUOUS_CURRENT: 0.14A; CaptureCellPackProp: Q_FET_N_ENH##1; DEVICE_TYPENAME: Q_FET_N_ENH_DFN1006-DMN26D0UFB420V999MOHM10V3000MOHM45V4000MOHM25V014A0805A10V035W999NC10V0NC45VB; DRAWING: @P3449_B01_LIB.P3449_B01(SCH_1):PAGE14; MAX_CURRENT: 0.805A; MAX_VOLTAGE: 20V; MAX_WATTAGE: 0.35W; NV_NAME: DMN26D0UFB4; NV_PN: 300-0868-000; PACK_TYPE: DFN1006; PATH: I114; PHYS_PAGE: 14; Q_G: 999nC@10V / 0nC@4.5V / 999nC@2.5V; ROT: 0; R_DS_ON: 999mohm@10V / 3000mohm@4.5V / 4000mohm@2.5V; SEC: 1; VER: 2; V_BE_GS: 10V; XY: (-10550,3400)
R144 = R: ASSEMBLY: M2_WIFIBT; CDS_LIB: discrete; CDS_PART_NAME: R_0402-47K,5 %,62.5MW,195-0599-000; CDS_PHYS_PART_NAME: R_0402-47K,5 %,62.5MW,195-0599-000-195-0599-000,47K; CDS_SEC: 1; DEVICE_TYPENAME: R_0402-47K5625MW195-0599-000-195-0599-00047K; DRAWING: @P3449_B01_LIB.P3449_B01(SCH_1):PAGE14; MAX_WATTAGE: 62.5mW; NV_PN: 195-0599-000; PATH: I31; PHYS_PAGE: 14; ROT: 0; SEC: 1; SIGNAL_MODEL: nv_res; SKU: NO STUFF; TOL: 5%; VER: 2; XY: (-3900,6900)
R320 = R#1: ASSEMBLY: M2_WIFIBT; CDS_LIB: discrete; CDS_PART_NAME: R_0402-47K,5 %,62.5MW,195-0599-000; CDS_PHYS_PART_NAME: R_0402-47K,5 %,62.5MW,195-0599-000-195-0599-000,47K; CDS_SEC: 1; CHIPS_PART_NAME: R; DEVICE_TYPENAME: R_0402-47K5625MW195-0599-000-195-0599-00047K; DRAWING: @P3449_B01_LIB.P3449_B01(SCH_1):PAGE14; MAX_WATTAGE: 62.5mW; NV_PN: 195-0599-000; PATH: I77; PHYS_PAGE: 14; ROT: 0; SEC: 1; SIGNAL_MODEL: nv_res; TOL: 5%; VER: 1; XY: (-8500,7000)
R378 = R: ASSEMBLY: M2_WIFIBT; CDS_LIB: discrete; CDS_PART_NAME: R_0402-47K,5 %,62.5MW,195-0599-000; CDS_PHYS_PART_NAME: R_0402-47K,5 %,62.5MW,195-0599-000-195-0599-000,47K; CDS_SEC: 1; DEVICE_TYPENAME: R_0402-47K5625MW195-0599-000-195-0599-00047K; DRAWING: @P3449_B01_LIB.P3449_B01(SCH_1):PAGE14; MAX_WATTAGE: 62.5mW; NV_PN: 195-0599-000; PATH: I138; PHYS_PAGE: 14; ROT: 0; SEC: 1; SIGNAL_MODEL: nv_res; TOL: 5%; VER: 2; XY: (-9850,4050)
R379 = R#1: ASSEMBLY: M2_WIFIBT; CDS_LIB: discrete; CDS_PART_NAME: R_0402-47K,5 %,62.5MW,195-0599-000; CDS_PHYS_PART_NAME: R_0402-47K,5 %,62.5MW,195-0599-000-195-0599-000,47K; CDS_SEC: 1; CHIPS_PART_NAME: R; DEVICE_TYPENAME: R_0402-47K5625MW195-0599-000-195-0599-00047K; DRAWING: @P3449_B01_LIB.P3449_B01(SCH_1):PAGE14; MAX_WATTAGE: 62.5mW; NV_PN: 195-0599-000; PATH: I142; PHYS_PAGE: 14; ROT: 0; SEC: 1; SIGNAL_MODEL: nv_res; TOL: 5%; VER: 1; XY: (-7750,5850)
R380 = R: ASSEMBLY: M2_WIFIBT; CDS_LIB: discrete; CDS_PART_NAME: R_0402-47K,5 %,62.5MW,195-0599-000; CDS_PHYS_PART_NAME: R_0402-47K,5 %,62.5MW,195-0599-000-195-0599-000,47K; CDS_SEC: 1; DEVICE_TYPENAME: R_0402-47K5625MW195-0599-000-195-0599-00047K; DRAWING: @P3449_B01_LIB.P3449_B01(SCH_1):PAGE14; MAX_WATTAGE: 62.5mW; NV_PN: 195-0599-000; PATH: I139; PHYS_PAGE: 14; ROT: 0; SEC: 1; SIGNAL_MODEL: nv_res; TOL: 5%; VER: 2; XY: (-7450,4050)
R381 = R: ASSEMBLY: M2_WIFIBT; CDS_LIB: discrete; CDS_PART_NAME: R_0402-47K,5 %,62.5MW,195-0599-000; CDS_PHYS_PART_NAME: R_0402-47K,5 %,62.5MW,195-0599-000-195-0599-000,47K; CDS_SEC: 1; DEVICE_TYPENAME: R_0402-47K5625MW195-0599-000-195-0599-00047K; DRAWING: @P3449_B01_LIB.P3449_B01(SCH_1):PAGE14; MAX_WATTAGE: 62.5mW; NV_PN: 195-0599-000; PATH: I135; PHYS_PAGE: 14; ROT: 0; SEC: 1; SIGNAL_MODEL: nv_res; SKU: NO STUFF; TOL: 5%; VER: 2; XY: (-3600,6900)
R469 = R: ASSEMBLY: M2_WIFIBT; CDS_LIB: discrete; CDS_PART_NAME: R_0402-10K,5 %,62.5MW,195-0486-000; CDS_PHYS_PART_NAME: R_0402-10K,5 %,62.5MW,195-0486-000-10K,195-0486-000; CDS_SEC: 1; DEVICE_TYPENAME: R_0402-10K5625MW195-0486-000-10K195-0486-000; DRAWING: @P3449_B01_LIB.P3449_B01(SCH_1):PAGE14; MAX_WATTAGE: 62.5mW; NV_PN: 195-0486-000; PATH: I152; PHYS_PAGE: 14; ROT: 0; SEC: 1; SIGNAL_MODEL: nv_res; TOL: 5%; VER: 2; XY: (-9600,6100)
R479 = R#1: ASSEMBLY: M2_WIFIBT; CDS_LIB: discrete; CDS_PART_NAME: R_0603-0OHM,0.05 OHM,0MW,195-1765-000; CDS_PHYS_PART_NAME: R_0603-0OHM,0.05 OHM,0MW,195-1765-000-0OHM,195-1765-000; CDS_SEC: 1; CHIPS_PART_NAME: R; DEVICE_TYPENAME: R_0603-0OHM005OHM0MW195-1765-000-0OHM195-1765-000; DRAWING: @P3449_B01_LIB.P3449_B01(SCH_1):PAGE14; MAX_WATTAGE: 0mW; NV_PN: 195-1765-000; PATH: I153; PHYS_PAGE: 14; ROT: 0; SEC: 1; SIGNAL_MODEL: nv_res; SKU: NO STUFF; TOL: 0.05 ohm; VER: 1; XY: (-2700,3450)
R480 = R#1: ASSEMBLY: M2_WIFIBT; CDS_LIB: discrete; CDS_PART_NAME: R_0603-0OHM,0.05 OHM,0MW,195-1765-000; CDS_PHYS_PART_NAME: R_0603-0OHM,0.05 OHM,0MW,195-1765-000-0OHM,195-1765-000; CDS_SEC: 1; CHIPS_PART_NAME: R; DEVICE_TYPENAME: R_0603-0OHM005OHM0MW195-1765-000-0OHM195-1765-000; DRAWING: @P3449_B01_LIB.P3449_B01(SCH_1):PAGE14; MAX_WATTAGE: 0mW; NV_PN: 195-1765-000; PATH: I154; PHYS_PAGE: 14; ROT: 0; SEC: 1; SIGNAL_MODEL: nv_res; SKU: NO STUFF; TOL: 0.05 ohm; VER: 1; XY: (-2700,3250)
R525 = R: ASSEMBLY: M2_WIFIBT; CDS_LIB: discrete; CDS_PART_NAME: R_0402-47K,5 %,62.5MW,195-0599-000; CDS_PHYS_PART_NAME: R_0402-47K,5 %,62.5MW,195-0599-000-195-0599-000,47K; CDS_SEC: 1; DEVICE_TYPENAME: R_0402-47K5625MW195-0599-000-195-0599-00047K; DRAWING: @P3449_B01_LIB.P3449_B01(SCH_1):PAGE14; MAX_WATTAGE: 62.5mW; NV_PN: 195-0599-000; PATH: I99; PHYS_PAGE: 14; ROT: 0; SEC: 1; SIGNAL_MODEL: nv_res; SKU: NO STUFF; TOL: 5%; VER: 2; XY: (-9600,6800)
U62 = U_BUF_OD: ASSEMBLY: M2_WIFIBT; CDS_LIB: logic; CDS_PART_NAME: U_BUF_OD_SC70_5-74LVC1G07GW/SN74LVC1G07DCKRE4,BUFFER - OPEN DRAIN,115-0138-000; CDS_PHYS_PART_NAME: U_BUF_OD_SC70_5-74LVC1G07GW/SN74LVC1G07DCKRE4,BUFFER - OPEN DRAIN,115-0138-000-115-0138-000; CDS_SEC: 1; DEVICE_TYPENAME: U_BUF_OD_SC70_5-74LVC1G07GWSN74LVC1G07DCKRE4BUFFER-OPENDRAIN115-0138-000-115-0138-000; DRAWING: @P3449_B01_LIB.P3449_B01(SCH_1):PAGE14; FUNCTION: Buffer - Open Drain; NV_NAME: 74LVC1G07GW/SN74LVC1G07DCKRE4; NV_PN: 115-0138-000; PATH: I147; PHYS_PAGE: 14; ROT: 0; SEC: 1; VER: 1; XY: (-10750,5850)
C26 = C#1: ASSEMBLY: ETHERNET; CDS_LIB: discrete; CDS_PART_NAME: C_0402-0.1UF,X5R,10%,6.3V,039-0007-000; CDS_PHYS_PART_NAME: C_0402-0.1UF,X5R,10%,6.3V,039-0007-000-0.1UF,039-0007-000; CDS_SEC: 1; CHIPS_PART_NAME: C; DEVICE_TYPENAME: C_0402-01UFX5R1063V039-0007-000-01UF039-0007-000; DRAWING: @P3449_B01_LIB.P3449_B01(SCH_1):PAGE15; ESL: N/A; ESR: N/A; MAT: X5R; MAX_VOLTAGE: 6.3V; NV_PN: 039-0007-000; PATH: I342; PHYS_PAGE: 15; ROT: 0; SEC: 1; SIGNAL_MODEL: nv_cap; TOL: 10%; VER: 1; XY: (-3900,3400)
C197 = C#1: ASSEMBLY: ETHERNET; CDS_LIB: discrete; CDS_PART_NAME: C_0402-10NF,X5R,10%,16V,039-0024-000; CDS_PHYS_PART_NAME: C_0402-10NF,X5R,10%,16V,039-0024-000-039-0024-000,10NF; CDS_SEC: 1; CHIPS_PART_NAME: C; DEVICE_TYPENAME: C_0402-10NFX5R1016V039-0024-000-039-0024-00010NF; DRAWING: @P3449_B01_LIB.P3449_B01(SCH_1):PAGE15; MAT: X5R; MAX_VOLTAGE: 16V; NV_PN: 039-0024-000; PATH: I291; PHYS_PAGE: 15; ROT: 0; SEC: 1; SIGNAL_MODEL: nv_cap; TOL: 10%; VER: 1; XY: (-5050,3950)
C205 = C: ASSEMBLY: ETHERNET; CDS_LIB: discrete; CDS_PART_NAME: C_0402-100PF,C0G,5%,50V,035-0012-000; CDS_PHYS_PART_NAME: C_0402-100PF,C0G,5%,50V,035-0012-000-035-0012-000,100PF; CDS_SEC: 1; DEVICE_TYPENAME: C_0402-100PFC0G550V035-0012-000-035-0012-000100PF; DRAWING: @P3449_B01_LIB.P3449_B01(SCH_1):PAGE15; ESL: N/A; ESR: N/A; MAT: C0G; MAX_VOLTAGE: 50V; NV_PN: 035-0012-000; PATH: I416; PHYS_PAGE: 15; ROT: 0; SEC: 1; SIGNAL_MODEL: nv_cap; TOL: 5%; VER: 2; XY: (-1550,4900)
J38 = HDR_2X2: ANGLE: 0; ASSEMBLY: ETHERNET; CDS_LIB: electro_mechanic; CDS_PART_NAME: HDR_2X2_TH02-2202-04-S-02-5.84/2.54-HT-HSF,MALE,2.54MM,0,YES,NO,NO,500 V,3 A,074-0216-000; CDS_PHYS_PART_NAME: HDR_2X2_TH02-2202-04-S-02-5.84/2.54-HT-HSF,MALE,2.54MM,0,YES,NO,NO,500 V,3 A,074-0216-000-074-0216-000; CDS_SEC: 1; DEVICE_TYPENAME: HDR_2X2_TH02-2202-04-S-02-584254-HT-HSFMALE254MM0YESNONO500V3A074-0216-000-074-0216-000; DRAWING: @P3449_B01_LIB.P3449_B01(SCH_1):PAGE15; GENDER: MALE; LATCHING: NO; MAX_CURRENT: 3:00 上午; MAX_VOLTAGE: 500 V; NV_NAME: 2202-04-S-02-5.84/2.54-HT-HSF; NV_PN: 074-0216-000; PACK_TYPE: TH02; PATH: I417; PHYS_PAGE: 15; PITCH: 2.54MM; REFLOW: YES; ROT: 0; SEC: 1; SEC_TYPE: TH02; SHROUDED: NO; VER: 1; XY: (-10250,4550)
J43 = CON_RJ45: ANGLE: 90; ASSEMBLY: ETHERNET; CDS_LIB: electro_mechanic; CDS_PART_NAME: CON_RJ45_RJ45_POE-A70-112-331N126,FEMALE,1.27MM,90,NO,YES,YES,YES,YES,54 V,600 MA,064-0373-000; CDS_PHYS_PART_NAME: CON_RJ45_RJ45_POE-A70-112-331N126,FEMALE,1.27MM,90,NO,YES,YES,YES,YES,54 V,600 MA,064-0373-000-064-0373-000; CDS_SEC: 1; DEVICE_TYPENAME: CON_RJ45_RJ45_POE-A70-112-331N126FEMALE127MM90NOYESYESYESYES54V600MA064-0373-000-064-0373-000; DRAWING: @P3449_B01_LIB.P3449_B01(SCH_1):PAGE15; EMI_GROUND_TAB: YES; GENDER: FEMALE; LATCHING: YES; MAX_CURRENT: 600 mA; MAX_VOLTAGE: 54 V; NV_NAME: A70-112-331N126; NV_PN: 064-0373-000; PACK_TYPE: RJ45_POE; PATH: I421; PHYS_PAGE: 15; PITCH: 1.27mm; REFLOW: NO; ROT: 0; SEC: 1; SHIELDED: YES; SHROUDED: YES; VER: 15; XY: (-3550,4850)
R8 = R#1: ASSEMBLY: ETHERNET; CDS_LIB: discrete; CDS_PART_NAME: R_0603-0OHM,0.05 OHM,0MW,195-1765-000; CDS_PHYS_PART_NAME: R_0603-0OHM,0.05 OHM,0MW,195-1765-000-0OHM,195-1765-000; CDS_SEC: 1; CHIPS_PART_NAME: R; DEVICE_TYPENAME: R_0603-0OHM005OHM0MW195-1765-000-0OHM195-1765-000; DRAWING: @P3449_B01_LIB.P3449_B01(SCH_1):PAGE15; MAX_WATTAGE: 0mW; NV_PN: 195-1765-000; PATH: I345; PHYS_PAGE: 15; ROT: 0; SEC: 1; SIGNAL_MODEL: nv_res; TOL: 0.05 ohm; VER: 1; XY: (-1550,4550)
R10 = R#1: ASSEMBLY: ETHERNET; CDS_LIB: discrete; CDS_PART_NAME: R_0402-110OHM,5 %,62.5MW,195-0492-000; CDS_PHYS_PART_NAME: R_0402-110OHM,5 %,62.5MW,195-0492-000-110OHM,195-0492-000; CDS_SEC: 1; CHIPS_PART_NAME: R; DEVICE_TYPENAME: R_0402-110OHM5625MW195-0492-000-110OHM195-0492-000; DRAWING: @P3449_B01_LIB.P3449_B01(SCH_1):PAGE15; MAX_WATTAGE: 62.5mW; NV_PN: 195-0492-000; PATH: I320; PHYS_PAGE: 15; ROT: 0; SEC: 1; SIGNAL_MODEL: nv_res; TOL: 5%; VER: 1; XY: (-4100,2800)
R12 = R#1: ASSEMBLY: ETHERNET; CDS_LIB: discrete; CDS_PART_NAME: R_0402-0OHM,0.05 OHM,62.5MW,195-2655-000; CDS_PHYS_PART_NAME: R_0402-0OHM,0.05 OHM,62.5MW,195-2655-000-0OHM,195-2655-000; CDS_SEC: 1; CHIPS_PART_NAME: R; DEVICE_TYPENAME: R_0402-0OHM005OHM625MW195-2655-000-0OHM195-2655-000; DRAWING: @P3449_B01_LIB.P3449_B01(SCH_1):PAGE15; MAX_WATTAGE: 62.5mW; NV_PN: 195-2655-000; PATH: I392; PHYS_PAGE: 15; ROT: 0; SEC: 1; SIGNAL_MODEL: nv_res; TOL: 0.05 ohm; VER: 1; XY: (-1550,5100)
R40 = R#1: ASSEMBLY: ETHERNET; CDS_LIB: discrete; CDS_PART_NAME: R_0402-0OHM,0.05 OHM,62.5MW,195-2655-000; CDS_PHYS_PART_NAME: R_0402-0OHM,0.05 OHM,62.5MW,195-2655-000-0OHM,195-2655-000; CDS_SEC: 1; CHIPS_PART_NAME: R; DEVICE_TYPENAME: R_0402-0OHM005OHM625MW195-2655-000-0OHM195-2655-000; DRAWING: @P3449_B01_LIB.P3449_B01(SCH_1):PAGE15; MAX_WATTAGE: 62.5mW; NV_PN: 195-2655-000; PATH: I394; PHYS_PAGE: 15; ROT: 0; SEC: 1; SIGNAL_MODEL: nv_res; TOL: 0.05 ohm; VER: 1; XY: (-1550,4700)
R44 = R#1: ASSEMBLY: ETHERNET; CDS_LIB: discrete; CDS_PART_NAME: R_0402-120OHM,5 %,62.5MW,195-0499-000; CDS_PHYS_PART_NAME: R_0402-120OHM,5 %,62.5MW,195-0499-000-120OHM,195-0499-000; CDS_SEC: 1; CHIPS_PART_NAME: R; DEVICE_TYPENAME: R_0402-120OHM5625MW195-0499-000-120OHM195-0499-000; DRAWING: @P3449_B01_LIB.P3449_B01(SCH_1):PAGE15; MAX_WATTAGE: 62.5mW; NV_PN: 195-0499-000; PATH: I321; PHYS_PAGE: 15; ROT: 0; SEC: 1; SIGNAL_MODEL: nv_res; TOL: 5%; VER: 1; XY: (-4100,2700)
R45 = R#1: ASSEMBLY: ETHERNET; CDS_LIB: discrete; CDS_PART_NAME: R_0402-0OHM,0.05 OHM,62.5MW,195-2655-000; CDS_PHYS_PART_NAME: R_0402-0OHM,0.05 OHM,62.5MW,195-2655-000-0OHM,195-2655-000; CDS_SEC: 1; CHIPS_PART_NAME: R; DEVICE_TYPENAME: R_0402-0OHM005OHM625MW195-2655-000-0OHM195-2655-000; DRAWING: @P3449_B01_LIB.P3449_B01(SCH_1):PAGE15; MAX_WATTAGE: 62.5mW; NV_PN: 195-2655-000; PATH: I393; PHYS_PAGE: 15; ROT: 0; SEC: 1; SIGNAL_MODEL: nv_res; TOL: 0.05 ohm; VER: 1; XY: (-1550,5200)
R46 = R#1: ASSEMBLY: ETHERNET; CDS_LIB: discrete; CDS_PART_NAME: R_0603-0OHM,0.05 OHM,0MW,195-1765-000; CDS_PHYS_PART_NAME: R_0603-0OHM,0.05 OHM,0MW,195-1765-000-0OHM,195-1765-000; CDS_SEC: 1; CHIPS_PART_NAME: R; DEVICE_TYPENAME: R_0603-0OHM005OHM0MW195-1765-000-0OHM195-1765-000; DRAWING: @P3449_B01_LIB.P3449_B01(SCH_1):PAGE15; MAX_WATTAGE: 0mW; NV_PN: 195-1765-000; PATH: I344; PHYS_PAGE: 15; ROT: 0; SEC: 1; SIGNAL_MODEL: nv_res; TOL: 0.05 ohm; VER: 1; XY: (-1550,4450)
R47 = R#1: ASSEMBLY: ETHERNET; CDS_LIB: discrete; CDS_PART_NAME: R_0603-0OHM,0.05 OHM,0MW,195-1765-000; CDS_PHYS_PART_NAME: R_0603-0OHM,0.05 OHM,0MW,195-1765-000-0OHM,195-1765-000; CDS_SEC: 1; CHIPS_PART_NAME: R; DEVICE_TYPENAME: R_0603-0OHM005OHM0MW195-1765-000-0OHM195-1765-000; DRAWING: @P3449_B01_LIB.P3449_B01(SCH_1):PAGE15; MAX_WATTAGE: 0mW; NV_PN: 195-1765-000; PATH: I343; PHYS_PAGE: 15; ROT: 0; SEC: 1; SIGNAL_MODEL: nv_res; TOL: 0.05 ohm; VER: 1; XY: (-1550,4350)

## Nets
GND: C26.2 C197.2 C205.1 C270.2 C277.2 C278.2 C280.2 C509.2 C510.2 C511.2 C512.2 D69.2 D70.2 J18.1(GND_11) J18.7(GND_10) J18.18(GND_9) J18.33(GND_8) J18.39(GND_7) J18.45(GND_6) J18.51(GND_5) J18.57(GND_4) J18.63(GND_3) J18.69(GND_2) J18.75(GND_1) J18.76(GND_13) J18.77(GND_12) MEC5.1 Q32.1(S) Q32.4(S) Q33.2(S) Q504.2(S) R8.1 R12.1 R40.1 R45.1 R46.1 R47.1 U49.3(GND) U50.3(GND) U51.3(GND) U55.3(GND) U59.3(GND) U62.3(GND) ; also on sheet 1 3 4 5 6 7 11 12 13 14 15 16 19
VDD_1V8: R320.1 U62.5(VCC) ; also on sheet 3 4 6 7 11 19
VDD_3V3_SYS: C26.1 C509.1 C510.1 C511.1 C512.1 J18.2(3P3V_4) J18.4(3P3V_3) J18.72(3P3V_2) J18.74(3P3V_1) J43.15(P15) J43.17(P17) R144.1 R378.1 R379.1 R380.1 R381.1 R469.1 R525.1 ; also on sheet 3 4 5 6 7 11 18 19
VDD_5V_IN: R365.1 R373.1 R375.1 R441.1 R442.1 R444.1 U49.5(VCC) U50.5(VCC) U51.5(VCC) U55.1(OE) U55.5(VCC) U59.5(VCC) ; also on sheet 3 4 7 11 12 14 15 19
AP_PET0_N: C7.1 J18.37(PETNO)
AP_PET0_P: C9.1 J18.35(PETPO)
BT_M2_EN: Q504.1(G) ; also on sheet 18
BT_M2_WAKE_AP: J18.20(UART_WAKE*) R379.2 ; also on sheet 18
CGND: C205.2 J43.19(SHIELD1) J43.20(SHIELD2) R8.2 R12.2 R40.2 R45.2 R46.2 R47.2
FORCE_OFF*: U59.2(A) ; also on sheet 19
FORCE_OFF_DELAY: C270.1 Q32.5(G) Q32.6(D) R373.2
GBE_LED_ACT: R44.1 ; also on sheet 18
GBE_LED_LINK: R10.1 ; also on sheet 18
GBE_MDI0_N: J43.2(P2) ; also on sheet 18
GBE_MDI0_P: J43.1(P1) ; also on sheet 18
GBE_MDI1_N: J43.6(P6) ; also on sheet 18
GBE_MDI1_P: J43.3(P3) ; also on sheet 18
GBE_MDI2_N: J43.8(P8) ; also on sheet 18
GBE_MDI2_P: J43.7(P7) ; also on sheet 18
GBE_MDI3_N: J43.10(P10) ; also on sheet 18
GBE_MDI3_P: J43.9(P9) ; also on sheet 18
GREEN_LED: J43.16(P16) R10.2
I2C2_M2_SCL: J18.60(I2C_CLK) R479.2
I2C2_M2_SDA: J18.58(I2C_DATA) R480.2
I2C2_SCL: D70.1 R479.1 ; also on sheet 3 19
I2C2_SDA: D69.1 R480.1 ; also on sheet 3 19
I2S1_LRCK: J18.10(PCM_SYNC_125_WS) ; also on sheet 18
I2S1_SCLK: J18.8(PCM_CLK_12S_SCK) ; also on sheet 18
I2S1_SDIN: J18.12(PCM_IN_12S_SD_IN) ; also on sheet 18
I2S1_SDOUT: J18.14(PCM_OUT_12S_SD_OUT) ; also on sheet 18
LATCH_RESET: C278.1 Q32.3(D) R365.2 U49.1(OE) U51.2(IN2) U59.4(Y)
LATCH_SET: C277.1 R375.2 U50.1(IN1) ; also on sheet 3
LATCH_SET_BUT: R444.2 U49.4(Y) ; also on sheet 3
M2_E_ALERT: J18.62(ALERT*) R320.2 ; also on sheet 18
MCT: C197.1 J43.4(P4) J43.5(P5)
PCIE0_CLK_N: J18.49(REFCLKNO) ; also on sheet 17
PCIE0_CLK_P: J18.47(REFCLKPO) ; also on sheet 17
PCIE0_CLKREQ: J18.53(CLKREQO*) R144.2 ; also on sheet 17
PCIE0_RST: J18.52(PERST0*) R525.2 ; also on sheet 17
PCIE0_RX0_M2_N: J18.43(PERNO) ; also on sheet 17
PCIE0_RX0_M2_P: J18.41(PERPO) ; also on sheet 17
PCIE0_TX0_AP_N: C7.2 ; also on sheet 17
PCIE0_TX0_AP_P: C9.2 ; also on sheet 17
PCIE_WAKE: J18.55(PEWAKEO*) R381.2 ; also on sheet 17
POE_VC1: J38.2 J43.11(P11)
POE_VC2: J38.1 J43.12(P12)
POE_VC3: J38.4 J43.13(P13)
POE_VC4: J38.3 J43.14(P14)
POWER_EN: R506.2 U55.4(Y) ; also on sheet 19
POWER_EN_Q: D31.1(C) R377.1 R442.2 R506.1 U50.4(OUT*) U51.1(IN1)
POWER_EN_Q_BAR: R441.2 U50.2(IN2) U51.4(OUT*)
POWER_EN_Q_R: C280.1 D31.2(A) R377.2 U55.2(A)
PWR_BTN*: Q32.2(G) U49.2(A) ; also on sheet 3 19
SNN_COEX1: J18.48(COEX1)
SNN_COEX2: J18.46(COEX2)
SNN_COEX3: J18.44(COEX3)
SNN_LED1_L: J18.6(LED1*)
SNN_LED2_L: J18.16(LED2*)
SNN_M2_B_65: J18.65(RESERVED_PERP1)
SNN_M2_B_67: J18.67(RESERVED_PERN1)
SNN_M2_B_71: J18.71(RESERVED_REFCLKP1)
SNN_M2_B_73: J18.73(RESERVED_REFCLKN1)
SNN_M2_E_59: J18.59(RESERVED_PETP1)
SNN_M2_E_61: J18.61(RESERVED_PETN1)
SNN_M2_E_64: J18.64(RESERVED)
SNN_M2_E_66: J18.66(UIM_SWP_PERST1*)
SNN_M2_E_68: J18.68(UIM_POWER_SNK_CLKREQ1*)
SNN_M2_E_70: J18.70(UIM_POWER_SRC_GPIO1_PEWAKE1*)
SNN_M2_SDIO_CLK: J18.9(SDIO_CLK)
SNN_M2_SDIO_CMD: J18.11(SDIO_CMD)
SNN_M2_SDIO_D0: J18.13(SDIO_DATAO)
SNN_M2_SDIO_D1: J18.15(SDIO_DATA1)
SNN_M2_SDIO_D2: J18.17(SDIO_DATA2)
SNN_M2_SDIO_D3: J18.19(SDIO_DATA3)
SNN_M2_WIFI_M2_EN: J18.23(SDIO_RESET*)
SNN_M2_WIFI_M2_WAKE_AP: J18.21(SDIO_WAKE*)
SNN_VENDOR_DEFINED1: J18.42(VENDOR_DEFINED_1)
SNN_VENDOR_DEFINED2: J18.40(VENDOR_DEFINED_2)
SNN_VENDOR_DEFINED3: J18.38(VENDOR_DEFINED_3)
SUSCLK_32KHZ: U62.2(A) ; also on sheet 17
SUSCLK_32KHZ_BUF: J18.50(SUSCLK_32KHZ) R469.2 U62.4(Y)
UART0_CTS: J18.34(UART_CTS) ; also on sheet 19
UART0_RTS: J18.36(UART_RTS) ; also on sheet 19
UART0_RXD: J18.22(UART_RXD) ; also on sheet 19
UART0_TXD: J18.32(UART_TXD) ; also on sheet 19
USB2_AP_N: J18.5(USB_DM) ; also on sheet 18
USB2_AP_P: J18.3(USB_DP) ; also on sheet 18
W_DISABLE1: J18.56(W_DISABLE1*) Q33.3(D) R380.2
W_DISABLE1_CTRL: Q33.1(G) ; also on sheet 18
W_DISABLE2: J18.54(W_DISABLE2*) Q504.3(D) R378.2
YELLOW_LED: J43.18(P18) R44.2

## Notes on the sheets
sheet 8
- A
- B
- C
- D
- E
- F
- G
- H
- Gigabit Ethernet with PoE
- 1
- 1
- 2
- Sprinkle around CGND shape
- 2
- For PoE
- 3
- 3
- If = 10mA
- GRN LED: Vf = 2.2V
- YEL LED: Vf = 2.1V
- 4
- 4
- 5
- 5
- NVIDIA CORPORATION
- 2701 SAN TOMAS
  EXPRESSWAY
- ASSEMBLY
- <ASSEMBLY_DESCRIPTION>
- SANTA CLARA, CA 95050, USA
- PAGE DETAIL
- Gigabit Ethernet POE
- NV_PN
- 600-13449-BASE-400
- ALL NVIDIA DESIGN SPECIFICATIONS, REFERENCE SPECIFICATIONS, REFERENCE BOARDS, FILES, DRAWINGS, DIAGNOSTICS, LISTS AND OTHER DOCUMENTS OR INFORMATION (TOGETHER AND SEPARATELY, 'MATERIALS') ARE BEING PROVIDED 'AS IS'. THE MATERIALS
  MAY
- CONTAIN KNOWN AND UNKNOWN VIOLATIONS OR DEVIATIONS OF INDUSTRY STANDARDS AND SPECIFICATIONS. NVIDIA MAKES NO WARRANTIES, EXPRESSED, IMPLIED, STATUTORY OR OTHERWISE WITH RESPECT TO THE MATERIALS OR OTHERWISE, AND EXPRESSLY DISCLAIMS
  ALL
- PCB REV
- P3449-B01
- PAGE
- 15 OF 23
- IMPLIED WARRANTIES INCLUDING, WITHOUT LIMITATION, THE WARRANTIES OF DESIGN, OF NONINFRINGEMENT, MERCHANTABILITY OR FITNESS FOR A PARTICULAR PURPOSE, OR ARISING FROM A COURSE OF DEALING, TRADE USAGE, TRADE PRACTICE, OR INDUSTRY
  STANDARDS.
- BOM REV
- M
- DATE
- 08-OCT-2022
- A
- B
- C
- D
- E
- F
- G
- H
sheet 9
- A
- B
- C
- D
- E
- F
- G
- H
- M.2 KEY E
- 1
- 1
- +/-5%  2Amps
- 2
- 2
- 3
- 3
- M.2 Mechanical stand-off
- Place in the bottom of PCB
- 4
- 4
- 5
- 5
- NVIDIA CORPORATION
- 2701 SAN TOMAS
  EXPRESSWAY
- ASSEMBLY
- <ASSEMBLY_DESCRIPTION>
- SANTA CLARA, CA 95050, USA
- PAGE DETAIL
- M.2
  Key-E
- NV_PN
- 600-13449-BASE-400
- ALL NVIDIA DESIGN SPECIFICATIONS, REFERENCE SPECIFICATIONS, REFERENCE BOARDS, FILES, DRAWINGS, DIAGNOSTICS, LISTS AND OTHER DOCUMENTS OR INFORMATION (TOGETHER AND SEPARATELY, 'MATERIALS') ARE BEING PROVIDED 'AS IS'. THE MATERIALS
  MAY
- CONTAIN KNOWN AND UNKNOWN VIOLATIONS OR DEVIATIONS OF INDUSTRY STANDARDS AND SPECIFICATIONS. NVIDIA MAKES NO WARRANTIES, EXPRESSED, IMPLIED, STATUTORY OR OTHERWISE WITH RESPECT TO THE MATERIALS OR OTHERWISE, AND EXPRESSLY DISCLAIMS
  ALL
- PCB REV
- P3449-B01
- PAGE
- 14 OF 23
- IMPLIED WARRANTIES INCLUDING, WITHOUT LIMITATION, THE WARRANTIES OF DESIGN, OF NONINFRINGEMENT, MERCHANTABILITY OR FITNESS FOR A PARTICULAR PURPOSE, OR ARISING FROM A COURSE OF DEALING, TRADE USAGE, TRADE PRACTICE, OR INDUSTRY
  STANDARDS.
- BOM REV
- M
- DATE
- 08-OCT-2022
- A
- B
- C
- D
- E
- F
- G
- H
sheet 10
- A
- B
- C
- D
- E
- F
- G
- H
- Module Power ON/OFF logic
- 1
- 1
- JUMPER TO DISABLE
- AUTO POWER
  ON
- PAGE-4, J40
- 2
- 2
- 5V -> 3.5V
- 15ms delay
- 3
- 3
- TRUTH TABLE
- 4
- 4
- LATCH_SET->
- LATCH_RESET->
- 10s BUTTON PRESS FOR FORCE SHUTDOWN
- POWER_EN_Q->
- 5
- 5
- NVIDIA CORPORATION
- 2701 SAN TOMAS
  EXPRESSWAY
- ASSEMBLY
- <ASSEMBLY_DESCRIPTION>
- SANTA CLARA, CA 95050, USA
- PAGE DETAIL
- Power ON/OFF Logic
- NV_PN
- 600-13449-BASE-400
- ALL NVIDIA DESIGN SPECIFICATIONS, REFERENCE SPECIFICATIONS, REFERENCE BOARDS, FILES, DRAWINGS, DIAGNOSTICS, LISTS AND OTHER DOCUMENTS OR INFORMATION (TOGETHER AND SEPARATELY, 'MATERIALS') ARE BEING PROVIDED 'AS IS'. THE MATERIALS
  MAY
- CONTAIN KNOWN AND UNKNOWN VIOLATIONS OR DEVIATIONS OF INDUSTRY STANDARDS AND SPECIFICATIONS. NVIDIA MAKES NO WARRANTIES, EXPRESSED, IMPLIED, STATUTORY OR OTHERWISE WITH RESPECT TO THE MATERIALS OR OTHERWISE, AND EXPRESSLY DISCLAIMS
  ALL
- PCB REV
- P3449-B01
- PAGE
- 13 OF 23
- IMPLIED WARRANTIES INCLUDING, WITHOUT LIMITATION, THE WARRANTIES OF DESIGN, OF NONINFRINGEMENT, MERCHANTABILITY OR FITNESS FOR A PARTICULAR PURPOSE, OR ARISING FROM A COURSE OF DEALING, TRADE USAGE, TRADE PRACTICE, OR INDUSTRY
  STANDARDS.
- BOM REV
- M
- DATE
- 08-OCT-2022
- A
- B
- C
- D
- E
- F
- G
- H
